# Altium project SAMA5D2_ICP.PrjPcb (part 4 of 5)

## Sheet 10 - CAN & WiFi BT.SchDoc
size B; CompanyName: Microchip Technology Inc.; Organization: Microchip Technology; Address1: 2355 West Chandler Blvd.; Address2: Chandler, AZ  85224; Address4: USA; DocumentNumber: 11; SheetNumber: 11; SheetTotal: 15; SheetTitle: CAN & WiFi/BT
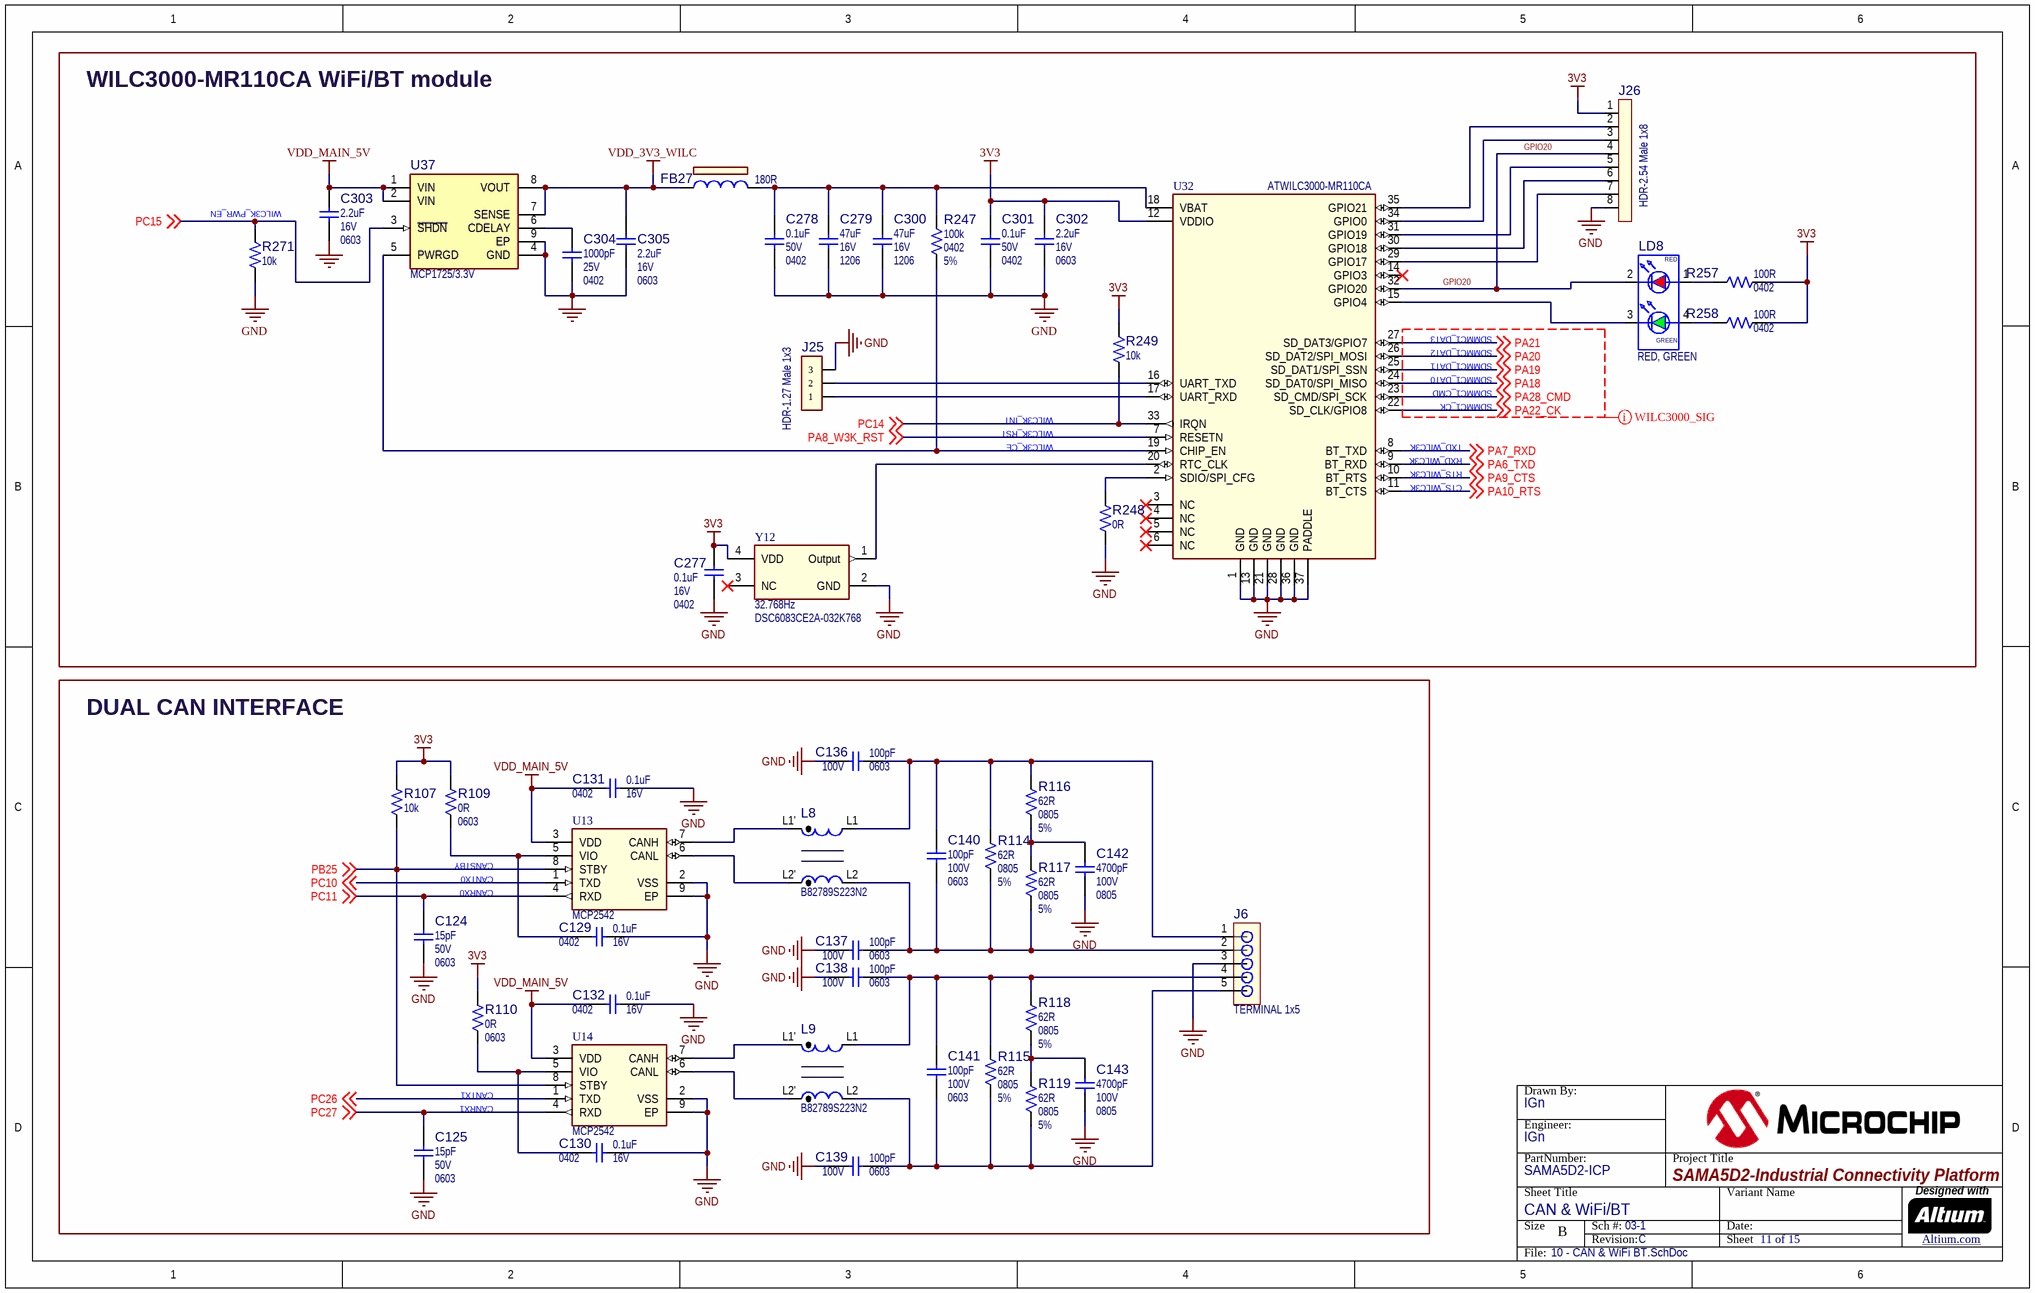
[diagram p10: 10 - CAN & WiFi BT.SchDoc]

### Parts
(Parts that share a designator on the sheet are numbered #1, #2 ... from top to bottom, then left to right.)
?#11  (no value)  (graphical)
C124  value 15pF  Voltage: 50V  Package: 0603  [CAP_C_0603]  (hidden comment: Capacitor NP)
C125  value 15pF  Voltage: 50V  Package: 0603  [CAP_C_0603]  (hidden comment: Capacitor NP)
C129  value 0.1uF  Voltage: 16V  Package: 0402  [CAP_C_0402]  (hidden comment: Capacitor NP)
C130  value 0.1uF  Voltage: 16V  Package: 0402  [CAP_C_0402]  (hidden comment: Capacitor NP)
C131  value 0.1uF  Voltage: 16V  Package: 0402  [CAP_C_0402]  (hidden comment: Capacitor NP)
C132  value 0.1uF  Voltage: 16V  Package: 0402  [CAP_C_0402]  (hidden comment: Capacitor NP)
C136  value 100pF  Voltage: 100V  Package: 0603  [CAP_C_0603]  (hidden comment: Capacitor NP)
C137  value 100pF  Voltage: 100V  Package: 0603  [CAP_C_0603]  (hidden comment: Capacitor NP)
C138  value 100pF  Voltage: 100V  Package: 0603  [CAP_C_0603]  (hidden comment: Capacitor NP)
C139  value 100pF  Voltage: 100V  Package: 0603  [CAP_C_0603]  (hidden comment: Capacitor NP)
C140  value 100pF  Voltage: 100V  Package: 0603  [CAP_C_0603]  (hidden comment: Capacitor NP)
C141  value 100pF  Voltage: 100V  Package: 0603  [CAP_C_0603]  (hidden comment: Capacitor NP)
C142  value 4700pF  Voltage: 100V  Package: 0805  [CAP_C_0805]  (hidden comment: Capacitor NP)
C143  value 4700pF  Voltage: 100V  Package: 0805  [CAP_C_0805]  (hidden comment: Capacitor NP)
C277  value 0.1uF  Voltage: 16V  Package: 0402  [CAP_C_0402]  (hidden comment: Capacitor NP)
C278  value 0.1uF  Voltage: 50V  Package: 0402  [CAP_C_0402]  (hidden comment: Capacitor NP)
C279  value 47uF  Voltage: 16V  Package: 1206  [CAP_C_1206]  (hidden comment: Capacitor NP)
C300  value 47uF  Voltage: 16V  Package: 1206  [CAP_C_1206]  (hidden comment: Capacitor NP)
C301  value 0.1uF  Voltage: 50V  Package: 0402  [CAP_C_0402]  (hidden comment: Capacitor NP)
C302  value 2.2uF  Voltage: 16V  Package: 0603  [CAP_C_0603]  (hidden comment: Capacitor NP)
C303  value 2.2uF  Voltage: 16V  Package: 0603  [CAP_C_0603]  (hidden comment: Capacitor NP)
C304  value 1000pF  Voltage: 25V  Package: 0402  [CAP_C_0402]  (hidden comment: Capacitor NP)
C305  value 2.2uF  Voltage: 16V  Package: 0603  [CAP_C_0603]  (hidden comment: Capacitor NP)
FB27  value 180R  [IND_C_0603]  (hidden comment: Ferrite Bead)
J6  value TERMINAL 1x5  [CON_TERMINAL_3.81_1x5_TH_RA_PHO_1727049]  (hidden comment: CON TERM BLK 1x5 TH Mount)
J25  value HDR-1.27 Male 1x3  [HDR_M_1.27_1x3]  (hidden comment: Header 1x3)
J26  value HDR-2.54 Male 1x8  [HDR_M_2.54_1x8]  (hidden comment: Header 1x8)
L8  value B82789S223N2  [IND_EP_SIMDAD_1812]  (hidden comment: Inductor Choke)
L9  value B82789S223N2  [IND_EP_SIMDAD_1812]  (hidden comment: Inductor Choke)
LD8  value RED, GREEN  [LED_DUAL_SMD_2x1.25mm]  (hidden comment: LED DUAL 4 pin)
R107  value 10k  [RES_C_0402]  (hidden comment: Resistor)
R109  value 0R  Package: 0603  [RES_C_0603]  (hidden comment: Resistor)
R110  value 0R  Package: 0603  [RES_C_0603]  (hidden comment: Resistor)
R114  value 62R  Package: 0805  Tolerance: 5%  [RES_C_0805]  (hidden comment: Resistor)
R115  value 62R  Package: 0805  Tolerance: 5%  [RES_C_0805]  (hidden comment: Resistor)
R116  value 62R  Package: 0805  Tolerance: 5%  [RES_C_0805]  (hidden comment: Resistor)
R117  value 62R  Package: 0805  Tolerance: 5%  [RES_C_0805]  (hidden comment: Resistor)
R118  value 62R  Package: 0805  Tolerance: 5%  [RES_C_0805]  (hidden comment: Resistor)
R119  value 62R  Package: 0805  Tolerance: 5%  [RES_C_0805]  (hidden comment: Resistor)
R247  value 100k  Package: 0402  Tolerance: 5%  [RES_C_0402]  (hidden comment: Resistor)
R248  value 0R  [RES_C_0603]  (hidden comment: Resistor)
R249  value 10k  [RES_C_0402]  (hidden comment: Resistor)
R257  value 100R  Package: 0402  [RES_C_0402]  (hidden comment: Resistor)
R258  value 100R  Package: 0402  [RES_C_0402]  (hidden comment: Resistor)
R271  value 10k  [RES_C_0402]  (hidden comment: Resistor)
U13  value MCP2542  [DFN-8_3x3_EP2.4X1.55]  (hidden comment: MCP2542 DFN-8)
U14  value MCP2542  [DFN-8_3x3_EP2.4X1.55]  (hidden comment: MCP2542 DFN-8)
U32  value ATWILC3000-MR110CA  [MODULE ATWILC3000-MR110CA]  (hidden comment: MODULE ATWILC3000-MR110CA)
U37  value MCP1725/3.3V  [DFN-8_2x3]  (hidden comment: MCP172X FIX DFN-8)
Y12  value 32.768Hz  Manufacturer Part Number 1: DSC6083CE2A-032K768  [OSCILLATOR_DSC1001_L3.2W2.5H0.85]  (hidden comment: OSC_DSC6083CE2A_3225)

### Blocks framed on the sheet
WILC3000-MR110CA WiFi/BT module: C277-C279 C300-C305 FB27 J25 J26 LD8 R247-R249 R257 R258 R271 U32 U37 Y12
DUAL CAN INTERFACE: C124 C125 C129-C132 C136-C143 J6 L8 L9 R107 R109 R110 R114-R119 U13 U14

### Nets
3V3: C277.2 C301.1 C302.2 J26.1 R107.2 R109.2 R110.2 R249.2 R257.2 R258.2 U32.12(VDDIO) Y12.4(VDD)
GND: C124.1 C125.1 C129.1 C130.1 C131.1 C132.1 C136.2 C137.2 C138.2 C139.2 C142.1 C143.1 C277.1 C278.2 C279.2 C300.2 C301.2 C302.1 C303.2 C304.1 C305.1 J6.3 J25.3 J26.8 R248.2 R271.1 U13.2(VSS) U13.9(EP) U14.2(VSS) U14.9(EP) U32.1(GND) U32.13(GND) U32.21(GND) U32.28(GND) U32.36(GND) U32.37(PADDLE) U37.4(GND) U37.9(EP) Y12.2(GND)
VDD_3V3_WILC: C305.2 FB27.1 U37.7(SENSE) U37.8(VOUT)
VDD_MAIN_5V: C131.2 C132.2 C303.1 U13.3(VDD) U14.3(VDD) U37.1(VIN) U37.2(VIN)
GPIO20: J26.4 LD8.2(K1) U32.32(GPIO20)
PA6_TXD: U32.9(BT_RXD) ; off-sheet PA6_TXD
PA7_RXD: U32.8(BT_TXD) ; off-sheet PA7_RXD
PA8_W3K_RST: U32.7(RESETN) ; off-sheet PA8_W3K_RST
PA9_CTS: U32.10(BT_RTS) ; off-sheet PA9_CTS
PA10_RTS: U32.11(BT_CTS) ; off-sheet PA10_RTS
PA18: U32.24(SD_DAT0/SPI_MISO) ; off-sheet PA18
PA19: U32.25(SD_DAT1/SPI_SSN) ; off-sheet PA19
PA20: U32.26(SD_DAT2/SPI_MOSI) ; off-sheet PA20
PA21: U32.27(SD_DAT3/GPIO7) ; off-sheet PA21
PA22_CK: U32.22(SD_CLK/GPIO8) ; off-sheet PA22_CK
PA28_CMD: U32.23(SD_CMD/SPI_SCK) ; off-sheet PA28_CMD
PB25: R107.1 U13.8(STBY) U14.8(STBY) ; off-sheet PB25
PC10: U13.1(TXD) ; off-sheet PC10
PC11: C124.2 U13.4(RXD) ; off-sheet PC11
PC14: R249.1 U32.33(IRQN) ; off-sheet PC14
PC15: R271.2 U37.3(~{SHDN}) ; off-sheet PC15
PC26: U14.1(TXD) ; off-sheet PC26
PC27: C125.2 U14.4(RXD) ; off-sheet PC27
NetC129_2: C129.2 R109.1 U13.5(VIO)
NetC130_2: C130.2 R110.1 U14.5(VIO)
NetC136_1: C136.1 C140.2 J6.1 L8.L1 R114.2 R116.2
NetC137_1: C137.1 C140.1 J6.2 L8.L2 R114.1 R117.1
NetC138_1: C138.1 C141.2 J6.4 L9.L1 R115.2 R118.2
NetC139_1: C139.1 C141.1 J6.5 L9.L2 R115.1 R119.1
NetC142_2: C142.2 R116.1 R117.2
NetC143_2: C143.2 R118.1 R119.2
NetC278_1: C278.1 C279.1 C300.1 FB27.2 R247.2 U32.18(VBAT)
NetC304_2: C304.2 U37.6(CDELAY)
NetJ25_1: J25.1 U32.17(UART_RXD)
NetJ25_2: J25.2 U32.16(UART_TXD)
NetJ26_2: J26.2 U32.35(GPIO21)
NetJ26_3: J26.3 U32.34(GPIO0)
NetJ26_5: J26.5 U32.31(GPIO19)
NetJ26_6: J26.6 U32.30(GPIO18)
NetJ26_7: J26.7 U32.29(GPIO17)
NetL8_L1': L8.L1' U13.7(CANH)
NetL8_L2': L8.L2' U13.6(CANL)
NetL9_L1': L9.L1' U14.7(CANH)
NetL9_L2': L9.L2' U14.6(CANL)
NetLD8_1: LD8.1(A1) R257.1
NetLD8_3: LD8.3(K2) U32.15(GPIO4)
NetLD8_4: LD8.4(A2) R258.1
NetR247_1: R247.1 U32.19(CHIP_EN) U37.5(PWRGD)
NetR248_1: R248.1 U32.2(SDIO/SPI_CFG)
NetU32_20: U32.20(RTC_CLK) Y12.1(Output)

Not connected (* = marked no-connect by the designer): U32 3(NC)* 4(NC)* 5(NC)* 6(NC)* 14(GPIO3)*; Y12 3(NC)*

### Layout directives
net class WILC300_SIG: PA18, PA19, PA20, PA21, PA22_CK, PA28_CMD

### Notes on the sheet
- (near R271) WILC3K_PWR_EN
- SDMMC1_DAT3
- SDMMC1_DAT2
- SDMMC1_DAT1
- SDMMC1_DAT0
- WILC3K_INT
- WILC3K_RST
- WILC3K_CE
- (near U32) TXD_WILC3K
- SDMMC1_CMD
- SDMMC1_CK
- (near U32) RXD_WILC3K
- (near U32) RTS_WILC3K
- (near U32) CTS_WILC3K
- CANRX0
- CANTX0
- CANSTBY
- CANRX1
- CANTX1

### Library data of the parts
?#11 = Title Block B
C124 C125 = CAP0121: Capacitor; Manufacturer 1: TDK; Manufacturer Part Number 1: C1608C0G1H150J; Description_: CAP CER 15pF 50V 5% NP0 SMD 0603; Dev Tools Status: Production; Tolerance: 5%; Temperature Coeffcient: NP0; Type: Ceramic; Populated: Yes
C129-C132 C277 = CAP1033: Capacitor; Manufacturer 1: Murata; Manufacturer Part Number 1: GRM155R71C104KA88D; Description_: CAP CER 0.1uF 16V 10% X7R SMD 0402; Dev Tools Status: Production; Tolerance: 10%; Temperature Coeffcient: X7R; Type: Ceramic; Owner: Sompoch Loboonlert; Populated: Yes
C136-C139 = CAP1112: Capacitor; Manufacturer 1: KEMET; Manufacturer Part Number 1: C0603C101J1GACTU; Description_: CAP CER 100pF 100V 5% C0G SMD 0603; Dev Tools Status: Production; Tolerance: 5%; Temperature Coeffcient: C0G, NP0; Type: Ceramic; Populated: YES; Owner: Mihai T(M91442)
C140 C141 = CAP1112: Capacitor; Manufacturer 1: KEMET; Manufacturer Part Number 1: C0603C101J1GACTU; Description_: CAP CER 100pF 100V 5% C0G SMD 0603; Dev Tools Status: Production; Tolerance: 5%; Temperature Coeffcient: C0G, NP0; Type: Ceramic; Populated: DNP; Owner: Mihai T(M91442)
C142 C143 = CAP1272: Capacitor; Manufacturer 1: TDK Corporation; Manufacturer Part Number 1: C2012X7R2A472K085AE; Description_: CAP CER 4700pF 100V 10% X7R SMD 0805; Dev Tools Status: Production; Tolerance: 10%; Temperature Coeffcient: X7R; Type: Ceramic; Populated: YES; Owner: Jairuz Agang-ang
C278 C301 = CAP1463: Capacitor; Manufacturer 1: TDK Corporation; Manufacturer Part Number 1: C1005X7R1H104K050BB; Description_: CAP CER 0.1uF 50V 10% X7R SMD 0402; Dev Tools Status: Production; Tolerance: 10%; Temperature Coeffcient: X7R; Type: Ceramic; Owner: Jamus Griego; Populated: YES
C279 = CAP1331: Capacitor; Manufacturer 1: TDK Corporation; Manufacturer Part Number 1: C3216X5R1C476M160AB; Description_: CAP CER 47uF 16V 20% X5R SMD 1206; Dev Tools Status: Production; Tolerance: 20%; Temperature Coeffcient: X5R; Type: Ceramic; Owner: Bogdan Popescu; Populated: YES
C300 = CAP1331: Capacitor; Manufacturer 1: TDK Corporation; Manufacturer Part Number 1: C3216X5R1C476M160AB; Description_: CAP CER 47uF 16V 20% X5R SMD 1206; Dev Tools Status: Production; Tolerance: 20%; Temperature Coeffcient: X5R; Type: Ceramic; Owner: Bogdan Popescu; Populated: DNP
C302 C303 C305 = CAP0597: Capacitor; Manufacturer 1: TDK; Manufacturer Part Number 1: C1608X5R1C225K; Description_: CAP CER 2.2uF 16V 10% X5R SMD 0603; Dev Tools Status: Production; Tolerance: 10%; Temperature Coeffcient: X5R; Type: Ceramic; Populated: Yes
C304 = CAP0566: Capacitor; Manufacturer 1: TDK; Manufacturer Part Number 1: C1005C0G1E102J; Description_: CAP CER 1000pF 25V 5% C0G SMD 0402; Dev Tools Status: Production; Tolerance: 5%; Temperature Coeffcient: C0G; Type: Ceramic; Populated: Yes
FB27 = IND1453: FERRITE 180R 1.5A SMD 0603; Manufacturer 1: Murata Electronics North America; Manufacturer Part Number 1: BLM18PG181SN1D; Dev Tools Status: Production; Owner: Dragos Danaila; DCR: 0.09R; Test Frequency: 100MHz; Populated: YES
J6 = CON1693: Manufacturer 1: Phoenix Contact; Manufacturer Part Number 1: 1727049; Description_: CON TERMINAL 3.81mm 1x5 Female 16-30AWG 13.5A TH R/A; Dev Tools Status: Design; Owner: Ciprian Abramov; Voltage: 300; Current: 13.5A; Populated: YES
J25 = CON1345: Manufacturer 1: Samtec; Manufacturer Part Number 1: TMS-103-01-G-S; Description_: CON HDR-1.27 Male 1x3 Gold TH; Dev Tools Status: Production; Owner: Jamus Griego; Populated: DNP
J26 = CON1302: CON HDR-2.54 Female 1x8 Gold TH; Manufacturer 1: FCI; Manufacturer Part Number 1: 68001-108HLF; Description_: CON HDR-2.54 Male 1x8 Gold 5.84MH TH; Dev Tools Status: Production; Owner: Bogdan Popescu; Populated: DNP
L8 L9 = IND1156: Inductor; Manufacturer 1: EPCOS Inc; Description_: CHOKE DBL 22UH 250MA TIN SMD; Dev Tools Status: Design; Owner: Stephen Humberd; RMS Current: 250mA; Populated: YES
LD8 = DIODE1110: LED; Manufacturer 1: Kingbright Corp; Manufacturer Part Number 1: APHBM2012SURKCGKC; Description_: DIO LED BI RED, GREEN 1.95V, 2.1V 30mA 0805; Dev Tools Status: Production; Type: LED Bicolor; Forward Current: 30mA; Power: 75mW; Reverse Current: 10uA; Owner: Bogdan P (M91398); Populated: Yes
R107 R249 = RSMT1019: Manufacturer 1: Panasonic; Manufacturer Part Number 1: ERJ-2RKF1002X; Tolerance: 1%; Description_: RES TKF 10k 1% 1/10W SMD 0402; Dev Tools Status: Production; Voltage: 50V; Temperature Coeffcient: 100ppm/C; Power: 1/10W; Owner: Brent Lanphear; Populated: Yes
R109 R110 R248 = RSMT0001: Manufacturer 1: Panasonic; Manufacturer Part Number 1: ERJ-3GSY0R00V; Description_: RES TKF 0R 1/10W SMD 0603; Dev Tools Status: Production; Power: 1/10W; Populated: Yes
R114 R115 = RSMT1232: Manufacturer 1: Panasonic Electronic Components; Manufacturer Part Number 1: ERJ-P06J620V; Description_: RES TKF 62R 5% 1/2W SMD 0805; Dev Tools Status: Design; Voltage: 600V; Temperature Coeffcient: 200ppm; Current: 90mA; Power: 1/2W; Owner: Dragos Danaila; Populated: DNP
R116-R119 = RSMT1232: Manufacturer 1: Panasonic Electronic Components; Manufacturer Part Number 1: ERJ-P06J620V; Description_: RES TKF 62R 5% 1/2W SMD 0805; Dev Tools Status: Design; Voltage: 600V; Temperature Coeffcient: 200ppm; Current: 90mA; Power: 1/2W; Owner: Dragos Danaila; Populated: YES
R247 = RES2196: Manufacturer 1: Yageo; Manufacturer Part Number 1: RC0402JR-07100KL; Description_: RES TKF 100k 5% 1/16W SMD 0402; Dev Tools Status: Design; Temperature Coeffcient: 100ppm/C; Power: 1/16W; Owner: Ilie Galan; Populated: YES
R257 R258 = RES1436: Manufacturer 1: Panasonic Electronic Components; Manufacturer Part Number 1: ERJ-2RKF1000X; Tolerance: 1%; Description_: RES TKF 100R 1% 1/10W SMD 0402; Dev Tools Status: Production; Temperature Coeffcient: ±100ppm/°C; Power: 1/10W; Populated: YES
R271 = RSMT1019: Manufacturer 1: Panasonic; Manufacturer Part Number 1: ERJ-2RKF1002X; Tolerance: 1%; Description_: RES TKF 10k 1% 1/10W SMD 0402; Dev Tools Status: Production; Voltage: 50V; Temperature Coeffcient: 100ppm/C; Power: 1/10W; Owner: Brent Lanphear; Populated: DNP
U13 U14 = MIC7856: Manufacturer 1: Microchip Technology; Manufacturer Part Number 1: MCP2542FDT-E/MF; Description_: MCHP INTERFACE CAN MCP2542FDT-E/MF DFN-8; MAPS Description: CAN Transceiver; Dev Tools Status: Design; Owner: Ilie Galan; MPC: V7BC6YA7XA00; LeadContent: Pb-FREE; PackingMedia: T/R; Stage: REL; LeadCount: 8; PackageWidth: 3x3x0.9mm; ForceMinOrderQtyMult: True; MinOrderQty: 1; TempRange: -40C to +125C; tblDeviceFamilyID: 5993; DeviceType: Transceiver; OperatingVoltageMin: 4.5; OperatingVoltageMax: 5.5; StandbyCurrentMax: 15; OperatingCurrentMax: 10; PropDelayMax: 120; ShortCircuit: -58 to +58; TransientVoltage: -150 to +100; ESD: 13; ThermalShutdown: Yes; Masks: 0; CMR: +/-12; Comments: Flexible Data Rate Capable
U32 = MIC7405: Manufacturer 1: Microchip Technology; Description_: MCHP RF WI-FI 802.11b/g/n ATWILC3000-MR110CA; MAPS Description: SmartConnect WILC3000-MR110CA Module; Dev Tools Status: Design; Owner: Ilie Galan; tblDeviceFamilyID: 11256; FrequencyRange: 2.412-2.472 MHz; MaxSpeedMHz: 0; Populated: DNP
U37 = MIC2599: LDO; Manufacturer 1: Microchip; Manufacturer Part Number 1: MCP1725T-3302E/MC; Description_: MCHP ANALOG LDO 3.3V MCP1725T-3302E/MC DFN-8; MAPS Description: 500MA, LOW VOLTAGE LDO; Dev Tools Status: Production; MPC: GEAH1YB3XA33; LeadContent: Pb-FREE; PackingMedia: T/R; Stage: REL; LeadCount: 8; PackageWidth: 2x3x0.9mm; ForceMinOrderQtyMult: True; MinOrderQty: 1; TempRange: -40C to +125C; tblDeviceFamilyID: 1781; Populated: Yes
Y12 = MIC7476: Manufacturer 1: Microchip Technology; Description_: MCHP CLOCK OSCILLATOR SINGLE 32.768Hz DSC6083CE2A-032K768 SMD DFN-4; Dev Tools Status: Design; Owner: Dragos Danaila; Populated: YES

## Sheet 11 - On Board Memories.SchDoc
size B; CompanyName: Microchip Technology Inc.; Organization: Microchip Technology; Address1: 2355 West Chandler Blvd.; Address2: Chandler, AZ  85224; Address4: USA; DocumentNumber: 12; SheetNumber: 12; SheetTotal: 15; SheetTitle: On Board Memories
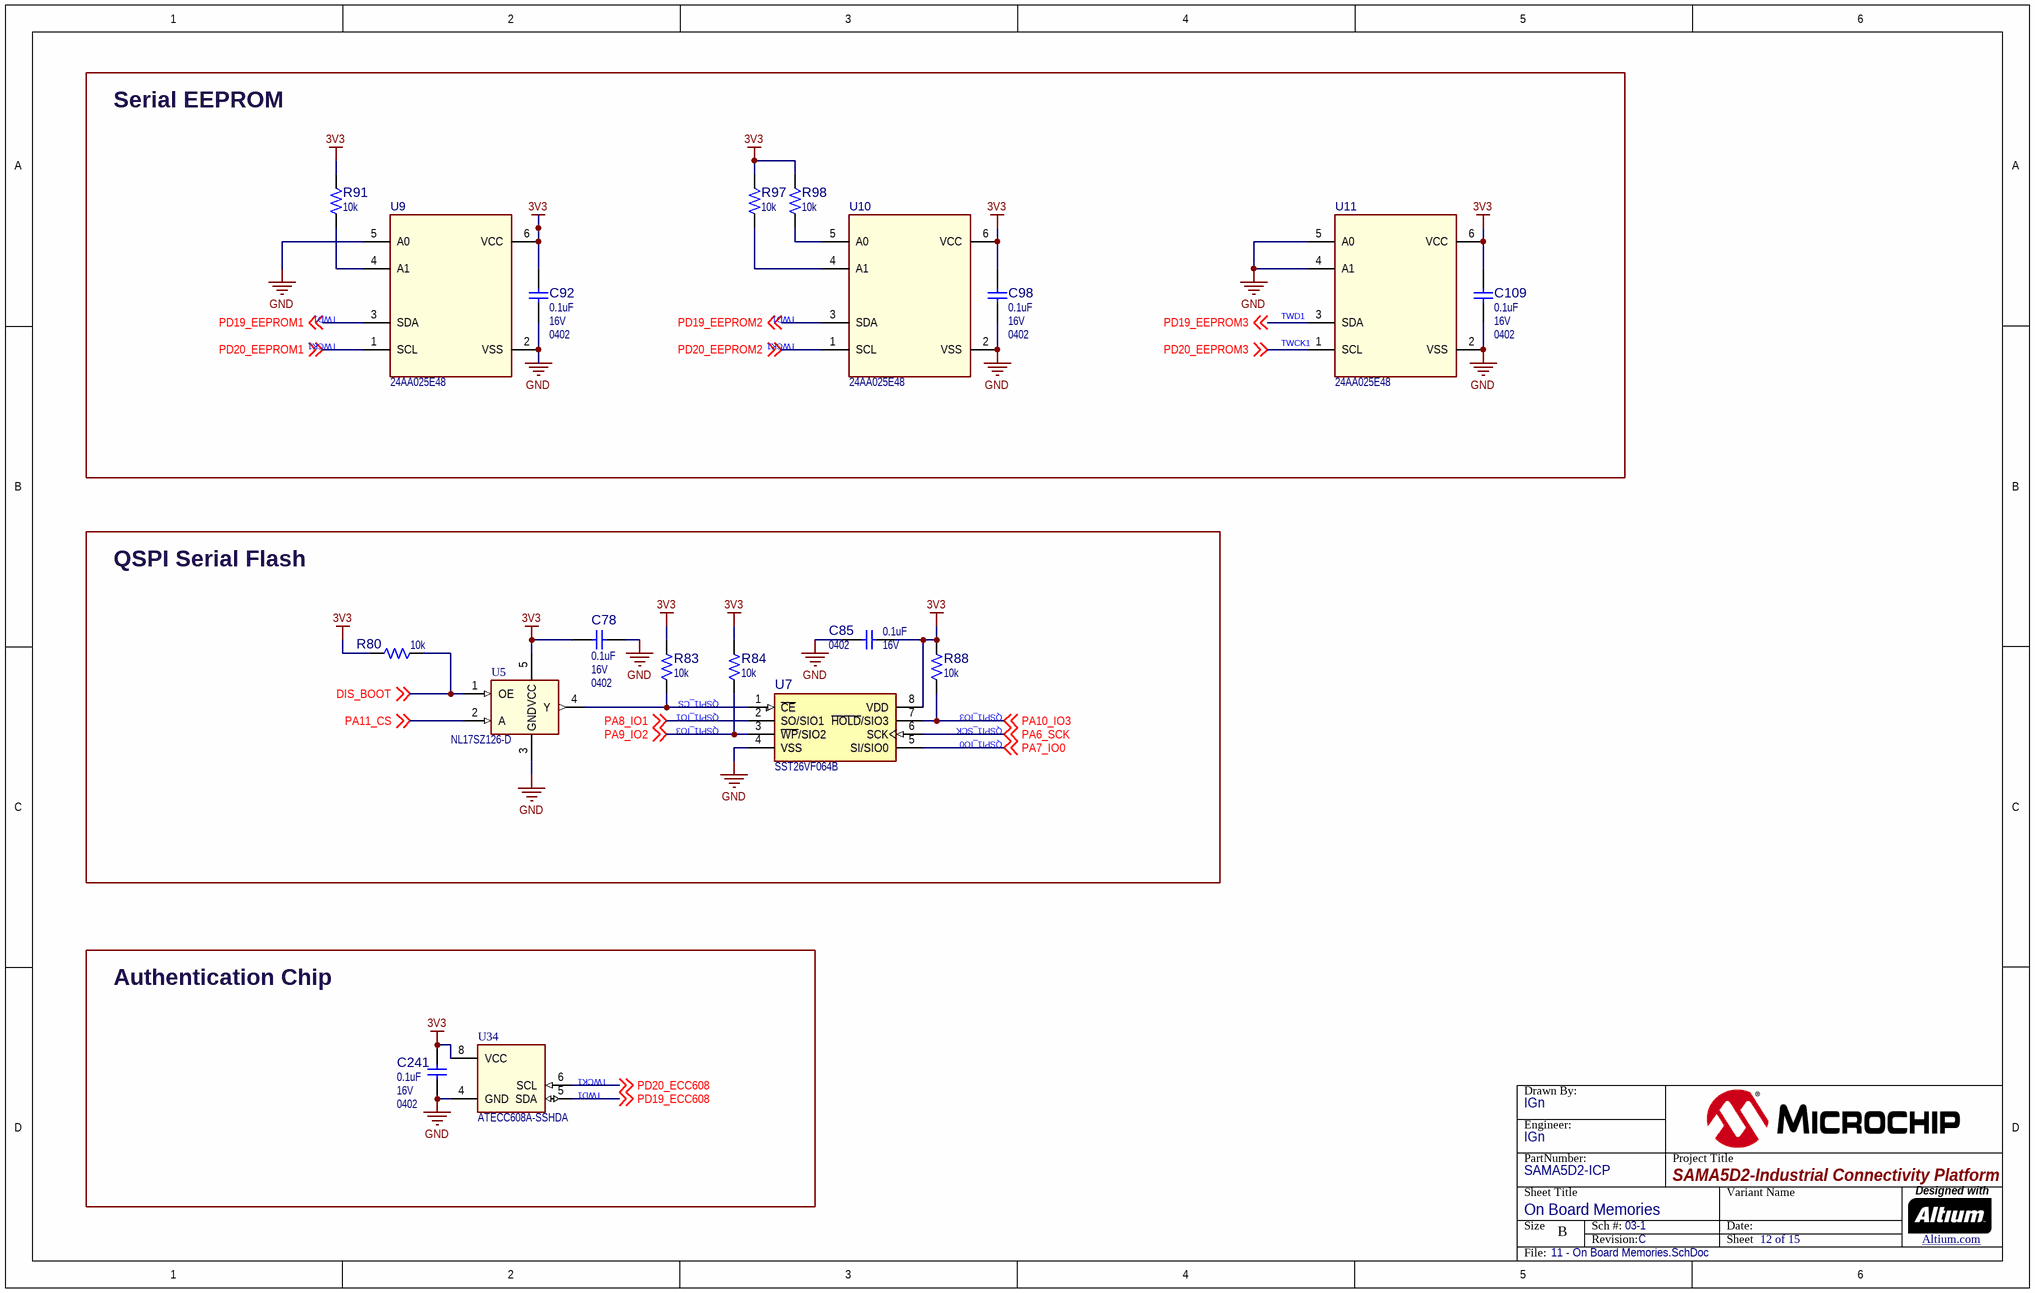
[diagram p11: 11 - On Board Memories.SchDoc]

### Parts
(Parts that share a designator on the sheet are numbered #1, #2 ... from top to bottom, then left to right.)
?#12  (no value)  (graphical)
C78  value 0.1uF  Voltage: 16V  Package: 0402  [CAP_C_0402]  (hidden comment: Capacitor NP)
C85  value 0.1uF  Voltage: 16V  Package: 0402  [CAP_C_0402]  (hidden comment: Capacitor NP)
C92  value 0.1uF  Voltage: 16V  Package: 0402  [CAP_C_0402]  (hidden comment: Capacitor NP)
C98  value 0.1uF  Voltage: 16V  Package: 0402  [CAP_C_0402]  (hidden comment: Capacitor NP)
C109  value 0.1uF  Voltage: 16V  Package: 0402  [CAP_C_0402]  (hidden comment: Capacitor NP)
C241  value 0.1uF  Voltage: 16V  Package: 0402  [CAP_C_0402]  (hidden comment: Capacitor NP)
R80  value 10k  [RES_C_0402]  (hidden comment: Resistor)
R83  value 10k  [RES_C_0402]  (hidden comment: Resistor)
R84  value 10k  [RES_C_0402]  (hidden comment: Resistor)
R88  value 10k  [RES_C_0402]  (hidden comment: Resistor)
R91  value 10k  [RES_C_0402]  (hidden comment: Resistor)
R97  value 10k  [RES_C_0402]  (hidden comment: Resistor)
R98  value 10k  [RES_C_0402]  (hidden comment: Resistor)
U5  value NL17SZ126-D  [SOT-353]  (hidden comment: NL17SZ126-D SOT-353)
U7  value SST26VF064B  [SOIJ-8]  (hidden comment: SST26VFXXX SOIC-8_WSON-8_SOIJ-8)
U9  value 24AA025E48  [SOT-23-6]  (hidden comment: 24XXXX SOT-23-6)
U10  value 24AA025E48  [SOT-23-6]  (hidden comment: 24XXXX SOT-23-6)
U11  value 24AA025E48  [SOT-23-6]  (hidden comment: 24XXXX SOT-23-6)
U34  value ATECC608A-SSHDA  [SOIC-8]  (hidden comment: ATECC608A-SSHDA-B SOIC-8)

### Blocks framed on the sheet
Serial EEPROM: C92 C98 C109 R91 R97 R98 U9-U11
QSPI Serial Flash: C78 C85 R80 R83 R84 R88 U5 U7
Authentication Chip: C241 U34

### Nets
3V3: C78.2 C85.2 C92.2 C98.2 C109.2 C241.2 R80.2 R83.2 R84.2 R88.2 R91.1 R97.2 R98.2 U5.5(VCC) U7.8(VDD) U9.6(VCC) U10.6(VCC) U11.6(VCC) U34.8(VCC)
GND: C78.1 C85.1 C92.1 C98.1 C109.1 C241.1 U5.3(GND) U7.4(VSS) U9.2(VSS) U9.5(A0) U10.2(VSS) U11.2(VSS) U11.4(A1) U11.5(A0) U34.4(GND)
DIS_BOOT: R80.1 U5.1(OE) ; off-sheet DIS_BOOT
PA6_SCK: U7.6(SCK) ; off-sheet PA6_SCK
PA7_IO0: U7.5(SI/SIO0) ; off-sheet PA7_IO0
PA8_IO1: U7.2(SO/SIO1) ; off-sheet PA8_IO1
PA9_IO2: R84.1 U7.3(~{WP}/SIO2) ; off-sheet PA9_IO2
PA10_IO3: R88.1 U7.7(~{HOLD}/SIO3) ; off-sheet PA10_IO3
PA11_CS: U5.2(A) ; off-sheet PA11_CS
PD19_ECC608: U34.5(SDA) ; off-sheet PD19_ECC608
PD19_EEPROM1: U9.3(SDA) ; off-sheet PD19_EEPROM1
PD19_EEPROM2: U10.3(SDA) ; off-sheet PD19_EEPROM2
PD19_EEPROM3: U11.3(SDA) ; off-sheet PD19_EEPROM3
PD20_ECC608: U34.6(SCL) ; off-sheet PD20_ECC608
PD20_EEPROM1: U9.1(SCL) ; off-sheet PD20_EEPROM1
PD20_EEPROM2: U10.1(SCL) ; off-sheet PD20_EEPROM2
PD20_EEPROM3: U11.1(SCL) ; off-sheet PD20_EEPROM3
NetR83_1: R83.1 U5.4(Y) U7.1(~{CE})
NetR91_2: R91.2 U9.4(A1)
NetR97_1: R97.1 U10.4(A1)
NetR98_1: R98.1 U10.5(A0)

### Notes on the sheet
- (near U9) TWD1
- (near U9) TWCK1
- (near U10) TWD1
- (near U10) TWCK1
- (near U11) TWD1
- (near U11) TWCK1
- QSPI1_IO1
- QSPI1_CS
- (near R88) QSPI1_IO3
- QSPI1_IO3
- QSPI1_IO0
- QSPI1_SCK
- (near U34) TWD1
- (near U34) TWCK1

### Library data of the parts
?#12 = Title Block B
C78 C85 C92 C98 C109 C241 = CAP1033: as C129-C132 on sheet 10 - CAN & WiFi BT
R80 R83 R84 R88 R91 R97 R98 = RSMT1019: as R107 on sheet 10 - CAN & WiFi BT
U5 = IC1434: Manufacturer 1: ON Semiconductor; Manufacturer Part Number 1: NL17SZ126DFT2G; MCHP-ID: IC1434; Description_: IC BUFFER NL17SZ126DFT2G TRI-ST NON-INV SOT-353; Dev Tools Status: Production; Vin: -0.5V to +7.0V; Owner: Alexandru Chiser - M19201; Populated: YES
U7 = MIC6216: SQI Serial Flash; Manufacturer 1: Microchip Technology; Manufacturer Part Number 1: SST26VF064B-104I/SM; Description_: MCHP SERIAL FLASH SST26VF064B-104I/SM SOIJ-8; MAPS Description: 64Mb 2.3V TO 3.6V SQI Flash Memory; Dev Tools Status: Production; Owner: Sompoch Loboonlert; MPC: S01027C3XA23; PackingMedia: TUBE; TempRange: -40C to +85C; Stage: REL; LeadCount: 8; PackageWidth: .208in; ForceMinOrderQtyMult: False; MinOrderQty: 0; LeadContent: Pb-FREE; Busmodes: SPI,SDI,SQI; MemorySize: 64Mb; OpVoltMin: 2,3; OpVoltMax: 3,6; MaxClockFreq: 104 MHz; PageSize_B: 256; WPScheme: Full Array; Endurance: 100,000; Populated: YES
U9-U11 = MIC7407: Manufacturer 1: Microchip Technology; Manufacturer Part Number 1: 24AA025E48T-I/OT; Description_: MCHP MEMORY SERIAL EEPROM 2Kb I2C 24AA025E48T-I/OT SOT-23-6; MAPS Description: 24AA025E48 device, which will be a pre-prog. version of the 24AA024H (DFAX7).; Dev Tools Status: Design; Owner: Ciprian Abramov; MPC: DFAX7TC8XD00; PackingMedia: T/R; TempRange: -40C to +85C; Stage: REL; LeadCount: 6; ForceMinOrderQtyMult: True; MinOrderQty: 50; LeadContent: Pb-FREE; MemorySize: 2K; OpVoltMin: 1.7; OpVoltMax: 5.5; MaxClockFreq: 400 kHz; AddressPins: 3; PageSize_B: 16; WPScheme: Half Array; MemoryOrg: x8; Endurance: 1,000,000; Comments: memory size changed from 2KBits to 2K; Populated: YES
U34 = MIC7054: Manufacturer 1: Microchip Technology; Description_: MCHP MEMORY SERIAL EEPROM CRYPTO I2C ATECC608A-SSHDA-B SOIC-8; Dev Tools Status: Production; Owner: Mark Loper; Populated: YES

## Sheet 12 - Expansion connectors.SchDoc
size B; CompanyName: Microchip Technology Inc.; Organization: Microchip Technology; Address1: 2355 West Chandler Blvd.; Address2: Chandler, AZ  85224; Address4: USA; DocumentNumber: 13; SheetNumber: 13; SheetTotal: 15; SheetTitle: Expansion connectors
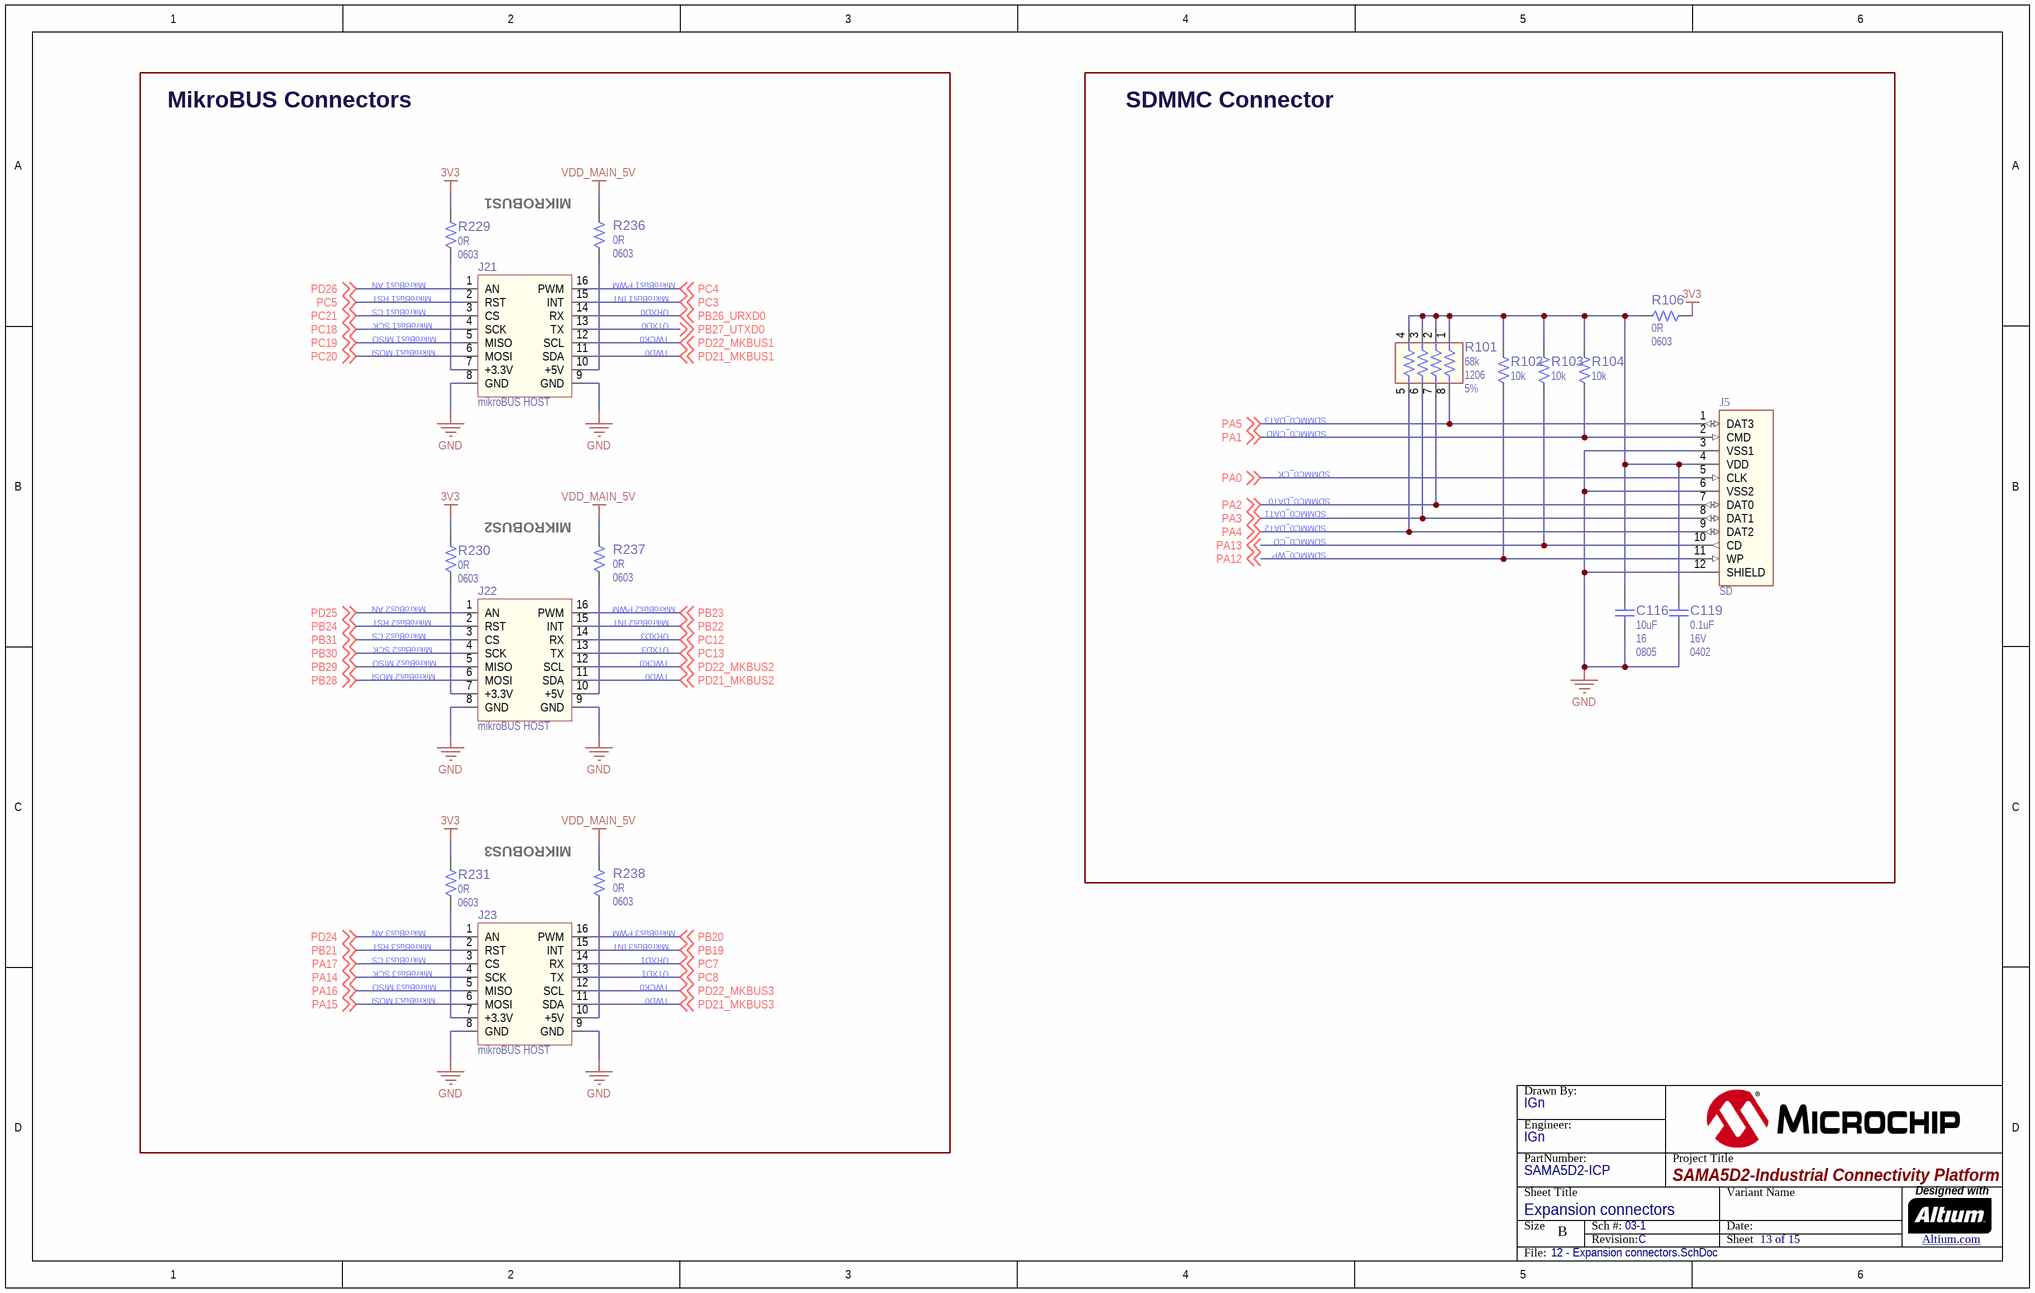
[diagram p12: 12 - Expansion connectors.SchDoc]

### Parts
(Parts that share a designator on the sheet are numbered #1, #2 ... from top to bottom, then left to right.)
?#13  (no value)  (graphical)
C116  value 10uF  Voltage: 16  Package: 0805  [CAP_C_0805]  (hidden comment: Capacitor NP)
C119  value 0.1uF  Voltage: 16V  Package: 0402  [CAP_C_0402]  (hidden comment: Capacitor NP)
J5  value SD  [10067847-001RLF]  (hidden comment: CON SD CARD 11P_amphenol)
J21  value mikroBUS HOST  [SOCKET_mikroBUS_F_2.54_2x8_V_25.4x21]  (hidden comment: SOCKET mikroBUS HOST)
J22  value mikroBUS HOST  [SOCKET_mikroBUS_F_2.54_2x8_V_25.4x21]  (hidden comment: SOCKET mikroBUS HOST)
J23  value mikroBUS HOST  [SOCKET_mikroBUS_F_2.54_2x8_V_25.4x21]  (hidden comment: SOCKET mikroBUS HOST)
R101  value 68k  Package: 1206  Tolerance: 5%  [RES_C_CAV_0603x4]  (hidden comment: Resistor Network 4-Ch)
R102  value 10k  [RES_C_0402]  (hidden comment: Resistor)
R103  value 10k  [RES_C_0402]  (hidden comment: Resistor)
R104  value 10k  [RES_C_0402]  (hidden comment: Resistor)
R106  value 0R  Package: 0603  [RES_C_0603]  (hidden comment: Resistor)
R229  value 0R  Package: 0603  [RES_C_0603]  (hidden comment: Resistor)
R230  value 0R  Package: 0603  [RES_C_0603]  (hidden comment: Resistor)
R231  value 0R  Package: 0603  [RES_C_0603]  (hidden comment: Resistor)
R236  value 0R  Package: 0603  [RES_C_0603]  (hidden comment: Resistor)
R237  value 0R  Package: 0603  [RES_C_0603]  (hidden comment: Resistor)
R238  value 0R  Package: 0603  [RES_C_0603]  (hidden comment: Resistor)

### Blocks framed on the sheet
MikroBUS Connectors: J21-J23 R229-R231 R236-R238
SDMMC Connector: C116 C119 J5 R101-R104 R106

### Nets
3V3: R106.1 R229.1 R230.1 R231.1
GND: C116.1 C119.1 J5.3(VSS1) J5.6(VSS2) J5.12(SHIELD) J21.8(GND) J21.9(GND) J22.8(GND) J22.9(GND) J23.8(GND) J23.9(GND)
VDD_MAIN_5V: R236.1 R237.1 R238.1
PA0: J5.5(CLK) ; off-sheet PA0
PA1: J5.2(CMD) R104.1 ; off-sheet PA1
PA2: J5.7(DAT0) R101.7 ; off-sheet PA2
PA3: J5.8(DAT1) R101.6 ; off-sheet PA3
PA4: J5.9(DAT2) R101.5 ; off-sheet PA4
PA5: J5.1(DAT3) R101.8 ; off-sheet PA5
PA12: J5.11(WP) R102.1 ; off-sheet PA12
PA13: J5.10(CD) R103.1 ; off-sheet PA13
PA14: J23.4(SCK) ; off-sheet PA14
PA15: J23.6(MOSI) ; off-sheet PA15
PA16: J23.5(MISO) ; off-sheet PA16
PA17: J23.3(CS) ; off-sheet PA17
PB19: J23.15(INT) ; off-sheet PB19
PB20: J23.16(PWM) ; off-sheet PB20
PB21: J23.2(RST) ; off-sheet PB21
PB22: J22.15(INT) ; off-sheet PB22
PB23: J22.16(PWM) ; off-sheet PB23
PB24: J22.2(RST) ; off-sheet PB24
PB26_URXD0: J21.14(RX) ; off-sheet PB26_URXD0
PB27_UTXD0: J21.13(TX) ; off-sheet PB27_UTXD0
PB28: J22.6(MOSI) ; off-sheet PB28
PB29: J22.5(MISO) ; off-sheet PB29
PB30: J22.4(SCK) ; off-sheet PB30
PB31: J22.3(CS) ; off-sheet PB31
PC3: J21.15(INT) ; off-sheet PC3
PC4: J21.16(PWM) ; off-sheet PC4
PC5: J21.2(RST) ; off-sheet PC5
PC7: J23.14(RX) ; off-sheet PC7
PC8: J23.13(TX) ; off-sheet PC8
PC12: J22.14(RX) ; off-sheet PC12
PC13: J22.13(TX) ; off-sheet PC13
PC18: J21.4(SCK) ; off-sheet PC18
PC19: J21.5(MISO) ; off-sheet PC19
PC20: J21.6(MOSI) ; off-sheet PC20
PC21: J21.3(CS) ; off-sheet PC21
PD21_MKBUS1: J21.11(SDA) ; off-sheet PD21_MKBUS1
PD21_MKBUS2: J22.11(SDA) ; off-sheet PD21_MKBUS2
PD21_MKBUS3: J23.11(SDA) ; off-sheet PD21_MKBUS3
PD22_MKBUS1: J21.12(SCL) ; off-sheet PD22_MKBUS1
PD22_MKBUS2: J22.12(SCL) ; off-sheet PD22_MKBUS2
PD22_MKBUS3: J23.12(SCL) ; off-sheet PD22_MKBUS3
PD24: J23.1(AN) ; off-sheet PD24
PD25: J22.1(AN) ; off-sheet PD25
PD26: J21.1(AN) ; off-sheet PD26
NetC116_2: C116.2 C119.2 J5.4(VDD) R101.1 R101.2 R101.3 R101.4 R102.2 R103.2 R104.2 R106.2
NetJ21_7: J21.7(+3.3V) R229.2
NetJ21_10: J21.10(+5V) R236.2
NetJ22_7: J22.7(+3.3V) R230.2
NetJ22_10: J22.10(+5V) R237.2
NetJ23_7: J23.7(+3.3V) R231.2
NetJ23_10: J23.10(+5V) R238.2

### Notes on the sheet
- (near R236) MIKROBUS1
- MikroBus1 AN
- MikroBus1 CS
- MikroBus1 RST
- URXD0
- MikroBus1 INT
- MikroBus1 PWM
- (near J21) MikroBus1 SCK
- (near J21) MikroBus1 MOSI
- (near J21) MikroBus1 MISO
- TWCK0
- TWD0
- UTXD0
- SDMMC0_CMD
- SDMMC0_DAT3
- SDMMC0_DAT1
- SDMMC0_DAT0
- SDMMC0_CK
- (near R237) MIKROBUS2
- SDMMC0_WP
- SDMMC0_CD
- SDMMC0_DAT2
- MikroBus2 AN
- MikroBus2 CS
- MikroBus2 RST
- (near J22) MikroBus2 SCK
- URXD3
- UTXD3
- MikroBus2 INT
- MikroBus2 PWM
- (near J22) MikroBus2 MOSI
- (near J22) MikroBus2 MISO
- (near R238) MIKROBUS3
- MikroBus3 AN
- MikroBus3 CS
- MikroBus3 RST
- (near J23) MikroBus3 SCK
- (near J23) MikroBus3 MISO
- URXD1
- UTXD1
- MikroBus3 INT
- MikroBus3 PWM
- (near J23) MikroBus3 MOSI

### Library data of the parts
?#13 = Title Block B
C116 = CAP1323: Capacitor; Manufacturer 1: Taiyo Yuden; Manufacturer Part Number 1: EMK212BB7106MG-T; Description_: CAP CER 10uF 16V 20% X7R SMD 0805; Dev Tools Status: Production; Tolerance: 20%; Temperature Coeffcient: X7R; Type: Ceramic; Owner: Rodger Griffith; Populated: YES
C119 = CAP1033: as C129-C132 on sheet 10 - CAN & WiFi BT
J5 = CON1752: Manufacturer 1: Amphenol FCI; Description_: 12 (9 + 3) Position Card Connector SD Surface Mount, Right Angle Gold; Dev Tools Status: Design; Owner: Dragos Danaila; Voltage: 17V; Current: 500mA; Populated: YES
J21-J23 = SKT1042: Manufacturer 1: Sullins Connector Solutions; Manufacturer Part Number 1: PPTC081LFBN-RC; Description_: SOCKET mikroBUS HOST DIP 16 TH; Dev Tools Status: Production; Owner: Stephen Humberd; Populated: YES
R101 = RNET1004: Resistor; Manufacturer 1: Yageo; Manufacturer Part Number 1: YC164-JR-0768KL; Description_: RES NET 68k 5% 62.5mW SMD 0603x4; Dev Tools Status: Production; Voltage: 50V; Temperature Coeffcient: 200ppm/C; Current: 1A; Power: 62.5mW; Owner: Alexandru Chiser - M19201; Populated: YES
R102-R104 = RSMT1019: as R107 on sheet 10 - CAN & WiFi BT
R106 R229-R231 = RSMT0001: as R109 on sheet 10 - CAN & WiFi BT
R236-R238 = RSMT0001: Manufacturer 1: Panasonic; Manufacturer Part Number 1: ERJ-3GSY0R00V; Description_: RES TKF 0R 1/10W SMD 0603; Dev Tools Status: Production; Power: 1/10W; Populated: YES

## Sheet 13 - User Command & Control.SchDoc
size B; CompanyName: Microchip Technology Inc.; Organization: Microchip Technology; Address1: 2355 West Chandler Blvd.; Address2: Chandler, AZ  85224; Address4: USA; DocumentNumber: 14; SheetNumber: 14; SheetTotal: 15; SheetTitle: User Command & Control
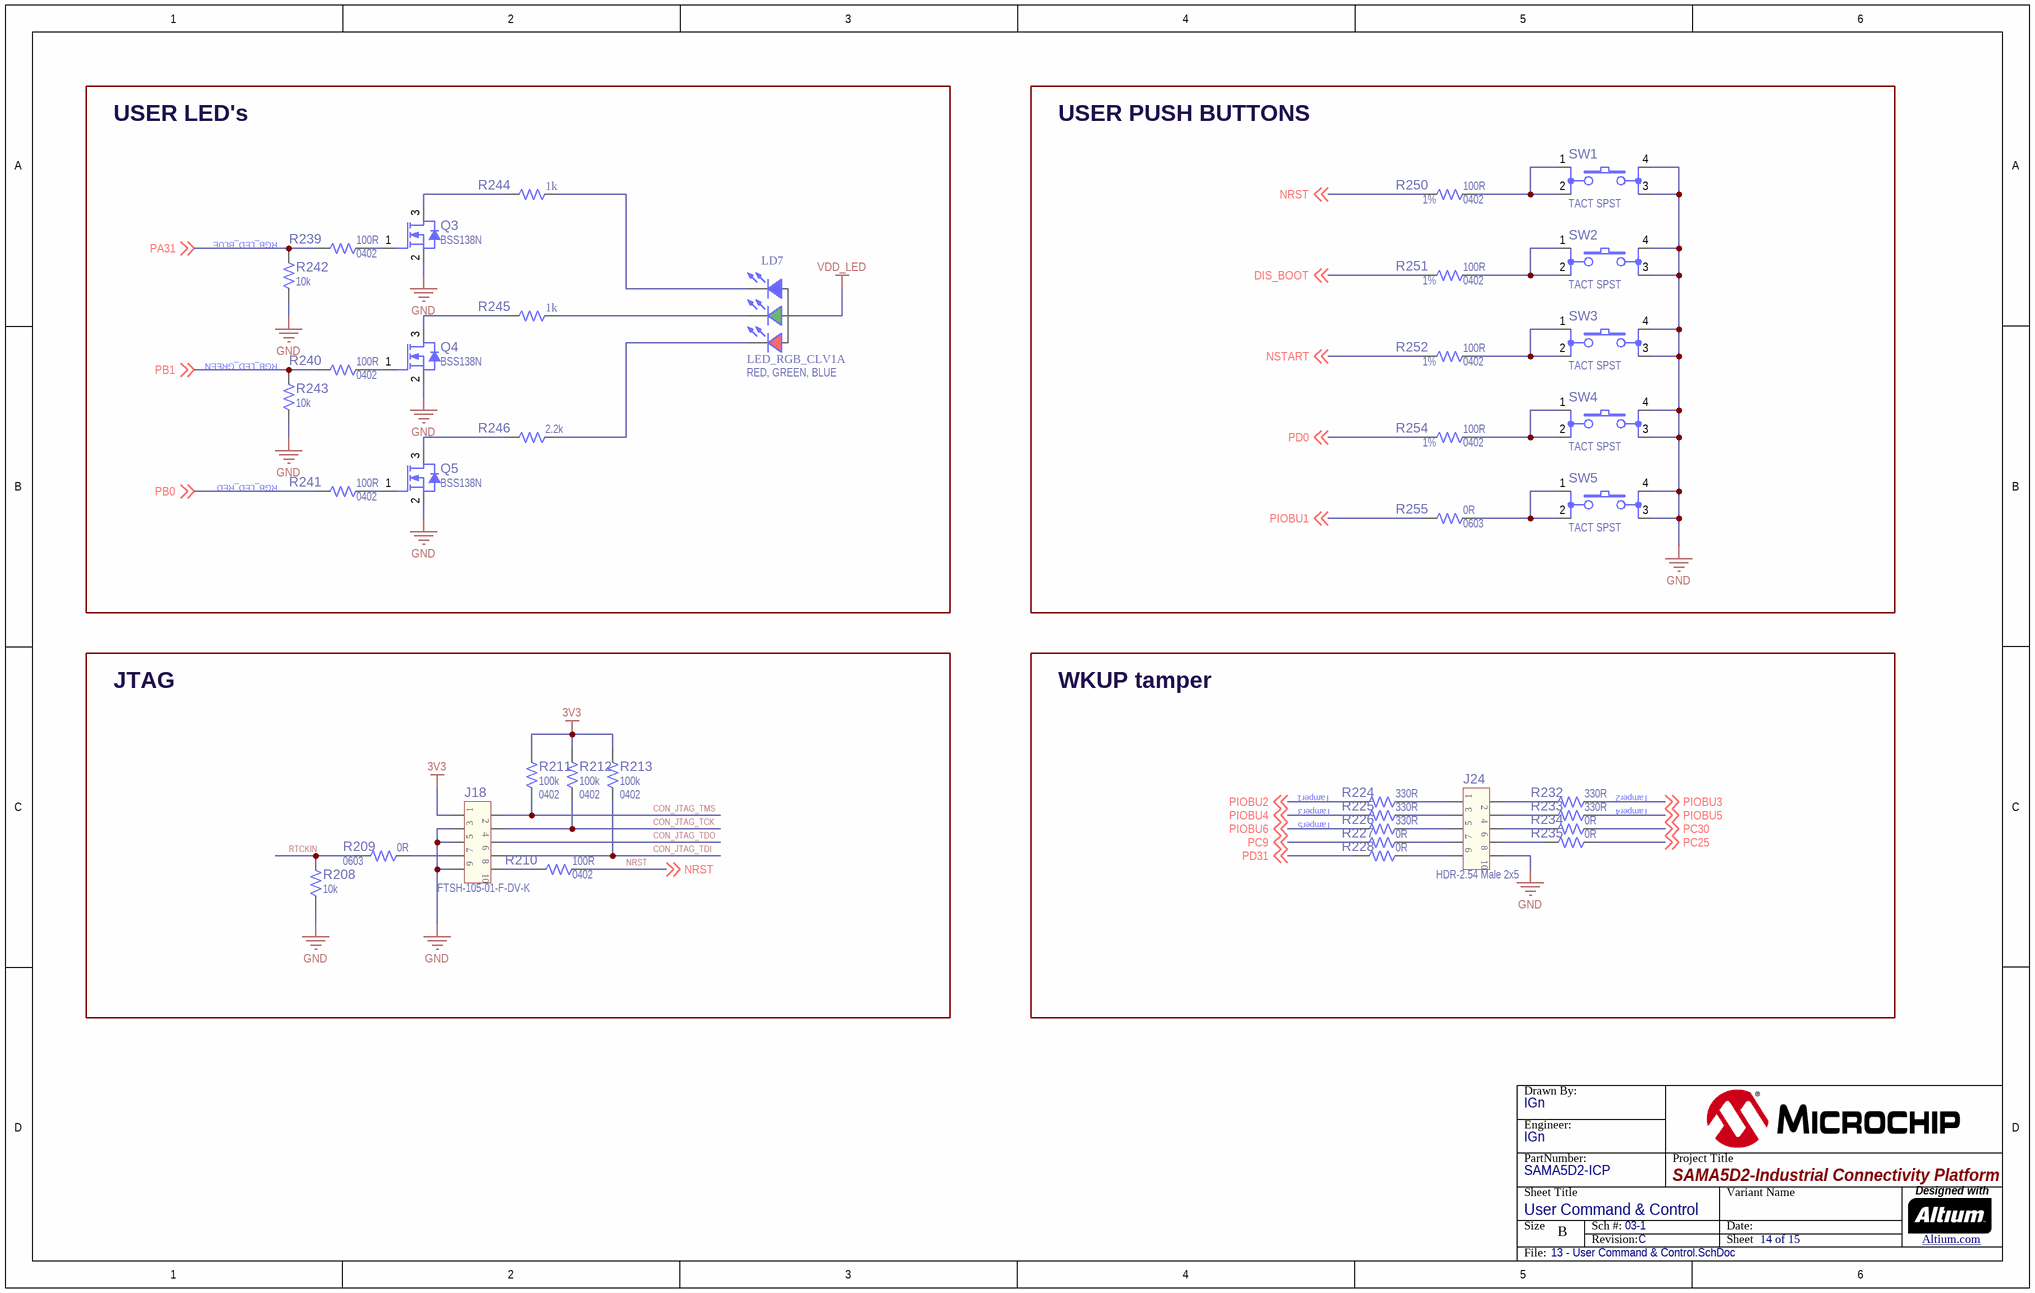
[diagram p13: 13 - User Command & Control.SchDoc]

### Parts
(Parts that share a designator on the sheet are numbered #1, #2 ... from top to bottom, then left to right.)
?#14  (no value)  (graphical)
J18  Manufacturer Part Number 1: FTSH-105-01-F-DV-K  [HDR_M_1.27_2x5_SMD_V_SAM_FTSH-105-01-F-DV-K]  (hidden comment: Header 2x5)
J24  value HDR-2.54 Male 2x5  [HDR_M_2.54_2x5_SMD_SAM_TSM-105-01-T-DV]  (hidden comment: Header 2x5)
LD7  LED_RGB_CLV1A  value RED, GREEN, BLUE  [PLCC-4_CLV1A-FKB]
Q3  value BSS138N  [SOT-23-3]  (hidden comment: Transistor MOS-N GSD)
Q4  value BSS138N  [SOT-23-3]  (hidden comment: Transistor MOS-N GSD)
Q5  value BSS138N  [SOT-23-3]  (hidden comment: Transistor MOS-N GSD)
R208  value 10k  [RES_C_0402]  (hidden comment: Resistor)
R209  value 0R  Package: 0603  [RES_C_0603]  (hidden comment: Resistor)
R210  value 100R  Package: 0402  [RES_C_0402]  (hidden comment: Resistor)
R211  value 100k  Package: 0402  [RES_C_0402]  (hidden comment: Resistor)
R212  value 100k  Package: 0402  [RES_C_0402]  (hidden comment: Resistor)
R213  value 100k  Package: 0402  [RES_C_0402]  (hidden comment: Resistor)
R224  value 330R  [RES_C_0603]  (hidden comment: Resistor)
R225  value 330R  [RES_C_0603]  (hidden comment: Resistor)
R226  value 330R  [RES_C_0603]  (hidden comment: Resistor)
R227  value 0R  [RES_C_0603]  (hidden comment: Resistor)
R228  value 0R  [RES_C_0603]  (hidden comment: Resistor)
R232  value 330R  [RES_C_0603]  (hidden comment: Resistor)
R233  value 330R  [RES_C_0603]  (hidden comment: Resistor)
R234  value 0R  [RES_C_0603]  (hidden comment: Resistor)
R235  value 0R  [RES_C_0603]  (hidden comment: Resistor)
R239  value 100R  Package: 0402  [RES_C_0402]  (hidden comment: Resistor)
R240  value 100R  Package: 0402  [RES_C_0402]  (hidden comment: Resistor)
R241  value 100R  Package: 0402  [RES_C_0402]  (hidden comment: Resistor)
R242  value 10k  [RES_C_0402]  (hidden comment: Resistor)
R243  value 10k  [RES_C_0402]  (hidden comment: Resistor)
R244  value 1k  [RES_C_0603]  (hidden comment: Resistor)
R245  value 1k  [RES_C_0603]  (hidden comment: Resistor)
R246  value 2.2k  [RES_C_0603]  (hidden comment: Resistor)
R250  value 100R  Package: 0402  Tolerance: 1%  [RES_C_0402]  (hidden comment: Resistor)
R251  value 100R  Package: 0402  Tolerance: 1%  [RES_C_0402]  (hidden comment: Resistor)
R252  value 100R  Package: 0402  Tolerance: 1%  [RES_C_0402]  (hidden comment: Resistor)
R254  value 100R  Package: 0402  Tolerance: 1%  [RES_C_0402]  (hidden comment: Resistor)
R255  value 0R  Package: 0603  [RES_C_0603]  (hidden comment: Resistor)
SW1  value TACT SPST  [SW_SMD_6mmX6mm_TL3301]  (hidden comment: Switch 4 Pin)
SW2  value TACT SPST  [SW_SMD_6mmX6mm_TL3301]  (hidden comment: Switch 4 Pin)
SW3  value TACT SPST  [SW_SMD_6mmX6mm_TL3301]  (hidden comment: Switch 4 Pin)
SW4  value TACT SPST  [SW_SMD_6mmX6mm_TL3301]  (hidden comment: Switch 4 Pin)
SW5  value TACT SPST  [SW_SMD_6mmX6mm_TL3301]  (hidden comment: Switch 4 Pin)

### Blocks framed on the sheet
USER LED's: LD7 Q3-Q5 R239-R246
USER PUSH BUTTONS: R250-R252 R254 R255 SW1-SW5
JTAG: J18 R208-R213
WKUP tamper: J24 R224-R228 R232-R235

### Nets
3V3: J18.1 R211.2 R212.2 R213.2
GND: J18.3 J18.5 J18.9 J24.10 Q3.2(S) Q4.2(S) Q5.2(S) R208.1 R242.1 R243.1 SW1.3 SW1.4 SW2.3 SW2.4 SW3.3 SW3.4 SW4.3 SW4.4 SW5.3 SW5.4
VDD_LED: LD7.2(A)
CON_JTAG_TCK: J18.4 R212.1
CON_JTAG_TDI: J18.8 R213.1
CON_JTAG_TDO: J18.6
CON_JTAG_TMS: J18.2 R211.1
DIS_BOOT: R251.1 ; off-sheet DIS_BOOT
NRST: R210.2 R250.1 ; off-sheet NRST
NSTART: R252.1 ; off-sheet NSTART
PA31: R239.1 R242.2 ; off-sheet PA31
PB0: R241.1 ; off-sheet PB0
PB1: R240.1 R243.2 ; off-sheet PB1
PC9: R227.2 ; off-sheet PC9
PC25: R235.1 ; off-sheet PC25
PC30: R234.2 ; off-sheet PC30
PD0: R254.1 ; off-sheet PD0
PD31: R228.2 ; off-sheet PD31
PIOBU1: R255.2 ; off-sheet PIOBU1
PIOBU2: R224.1 ; off-sheet PIOBU2
PIOBU3: R232.2 ; off-sheet PIOBU3
PIOBU4: R225.1 ; off-sheet PIOBU4
PIOBU5: R233.2 ; off-sheet PIOBU5
PIOBU6: R226.1 ; off-sheet PIOBU6
RTCKIN: R208.2 R209.2
NetJ18_7: J18.7 R209.1
NetJ18_10: J18.10 R210.1
NetJ24_1: J24.1 R224.2
NetJ24_2: J24.2 R232.1
NetJ24_3: J24.3 R225.2
NetJ24_4: J24.4 R233.1
NetJ24_5: J24.5 R226.2
NetJ24_6: J24.6 R234.1
NetJ24_7: J24.7 R227.1
NetJ24_8: J24.8 R235.2
NetJ24_9: J24.9 R228.1
NetLD7_1: LD7.1(Kr) R246.2
NetLD7_3: LD7.3(Kb) R244.2
NetLD7_4: LD7.4(Kg) R245.2
NetQ3_1: Q3.1(G) R239.2
NetQ3_3: Q3.3(D) R244.1
NetQ4_1: Q4.1(G) R240.2
NetQ4_3: Q4.3(D) R245.1
NetQ5_1: Q5.1(G) R241.2
NetQ5_3: Q5.3(D) R246.1
NetR250_2: R250.2 SW1.1 SW1.2
NetR251_2: R251.2 SW2.1 SW2.2
NetR252_2: R252.2 SW3.1 SW3.2
NetR254_2: R254.2 SW4.1 SW4.2
NetR255_1: R255.1 SW5.1 SW5.2

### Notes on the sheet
- (near R242) RGB_LED_BLUE
- (near R243) RGB_LED_GREEN
- RGB_LED_RED
- Tamper1
- Tamper3
- Tamper5
- Tamper2
- Tamper4

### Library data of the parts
?#14 = Title Block B
J18 = CON1047: CON HDR-1.27 Male 2x5 Gold 3.05MH SMD VERT; Manufacturer 1: Samtec; Dev Tools Status: Production; Owner: Tad Ahlvers; Populated: YES
J24 = CON1639: CON HDR-1.27 Male 2x5 Gold 3.05MH SMD VERT; Manufacturer 1: Samtec Inc.; Manufacturer Part Number 1: TSM-105-01-T-DV; Description_: CON HDR-2.54 Male 2x5 Tin 5.84MH SMD VERT; Dev Tools Status: Design; Owner: Gabor Bihari; Voltage: 475V; Current: 4.1A; Populated: DNP
LD7 = DIODE1214: Manufacturer 1: Cree Inc; Manufacturer Part Number 1: CLV1A-FKB-CK1N1G1BB7R4S3; Description_: DIO LED TRI RED, GREEN, BLUE 2V, 3.2V, 3.2V 20mA, 20mA, 20mA SMD 4-PLCC; Dev Tools Status: Production; Type: LED Tricolor; Forward Current: 20mA, 20mA, 20mA; Power: 130mW, 100mW, 100mW; Reverse Current: 10uA; Reverse Voltage: 5V; Owner: Randolph Sobrepena; Populated: YES
Q3-Q5 = TRA1223: Transistor MOS; Manufacturer 1: Infineon Technologies; Manufacturer Part Number 1: BSS138NH6327XTSA2; Description_: TRANS FET N-CH BSS138N 60V 230mA SOT23-3; Dev Tools Status: Production; Type: FET; Current: 230mA; Drain to Source Voltage: 60V; Gate to Source Voltage: 20V; Power: 0.36W; Owner: Dragos Danaila; Populated: YES
R208 R242 R243 = RSMT1019: as R107 on sheet 10 - CAN & WiFi BT
R209 = RSMT0001: Manufacturer 1: Panasonic; Manufacturer Part Number 1: ERJ-3GSY0R00V; Description_: RES TKF 0R 1/10W SMD 0603; Dev Tools Status: Production; Power: 1/10W; Populated: DNP
R210 R239-R241 = RES1436: as R257 on sheet 10 - CAN & WiFi BT
R211-R213 = RES1011: Manufacturer 1: Panasonic; Manufacturer Part Number 1: ERJ-2RKF1003X; Tolerance: 1%; Description_: RES TKF 100k 1% 1/10W SMD 0402; Dev Tools Status: Production; Voltage: 50V; Temperature Coeffcient: 100ppm/C; Power: 1/10W; Owner: Tad Ahlvers; Populated: YES
R224-R226 R232 R233 = RSMT0166: Manufacturer 1: Panasonic; Manufacturer Part Number 1: ERJ-3GEYJ331V; Tolerance: 5%; Description_: RES TKF 330R 5% 1/10W SMD 0603; Dev Tools Status: Production; Voltage: 75V; Temperature Coeffcient: 200ppm/C; Power: 1/10W; Populated: Yes
R227 R228 R234 R235 R255 = RSMT0001: as R109 on sheet 10 - CAN & WiFi BT
R244 R245 = RSMT0138: Manufacturer 1: Panasonic; Manufacturer Part Number 1: ERJ-3EKF1001V; Tolerance: 1%; Description_: RES TKF 1k 1% 1/10W SMD 0603; Dev Tools Status: Production; Voltage: 75V; Temperature Coeffcient: 100ppm/C; Power: 1/10W; Populated: Yes
R246 = RES1130: Manufacturer 1: Panasonic; Manufacturer Part Number 1: ERJ-3EKF2201V; Tolerance: 1%; Description_: RES TKF 2.2k 1% 1/10W SMD 0603; Dev Tools Status: Production; Voltage: 75V; Temperature Coeffcient: 100ppm/C; Power: 1/10W; Owner: Bogdan P (M91398); Populated: Yes
R250-R252 R254 = RES1436: Manufacturer 1: Panasonic Electronic Components; Manufacturer Part Number 1: ERJ-2RKF1000X; Description_: RES TKF 100R 1% 1/10W SMD 0402; Dev Tools Status: Production; Temperature Coeffcient: ±100ppm/°C; Power: 1/10W; Populated: YES
SW1-SW5 = SWITCH0077: Switch; Manufacturer 1: E-Switch; Manufacturer Part Number 1: TL3301AF260QG; Description_: SWITCH TACT SPST 12V 50mA TL3301AF260QG SMD; Dev Tools Status: Production; Voltage: 12V; Current: 50mA; Populated: Yes

## Sheet 14 - JLINK-OB Interface.SchDoc
size B; CompanyName: Microchip Technology Inc.; Organization: Microchip Technology; Address1: 2355 West Chandler Blvd.; Address2: Chandler, AZ  85224; Address4: USA; DocumentNumber: 15; SheetNumber: 15; SheetTotal: 15; SheetTitle: JLINK-OB Interface
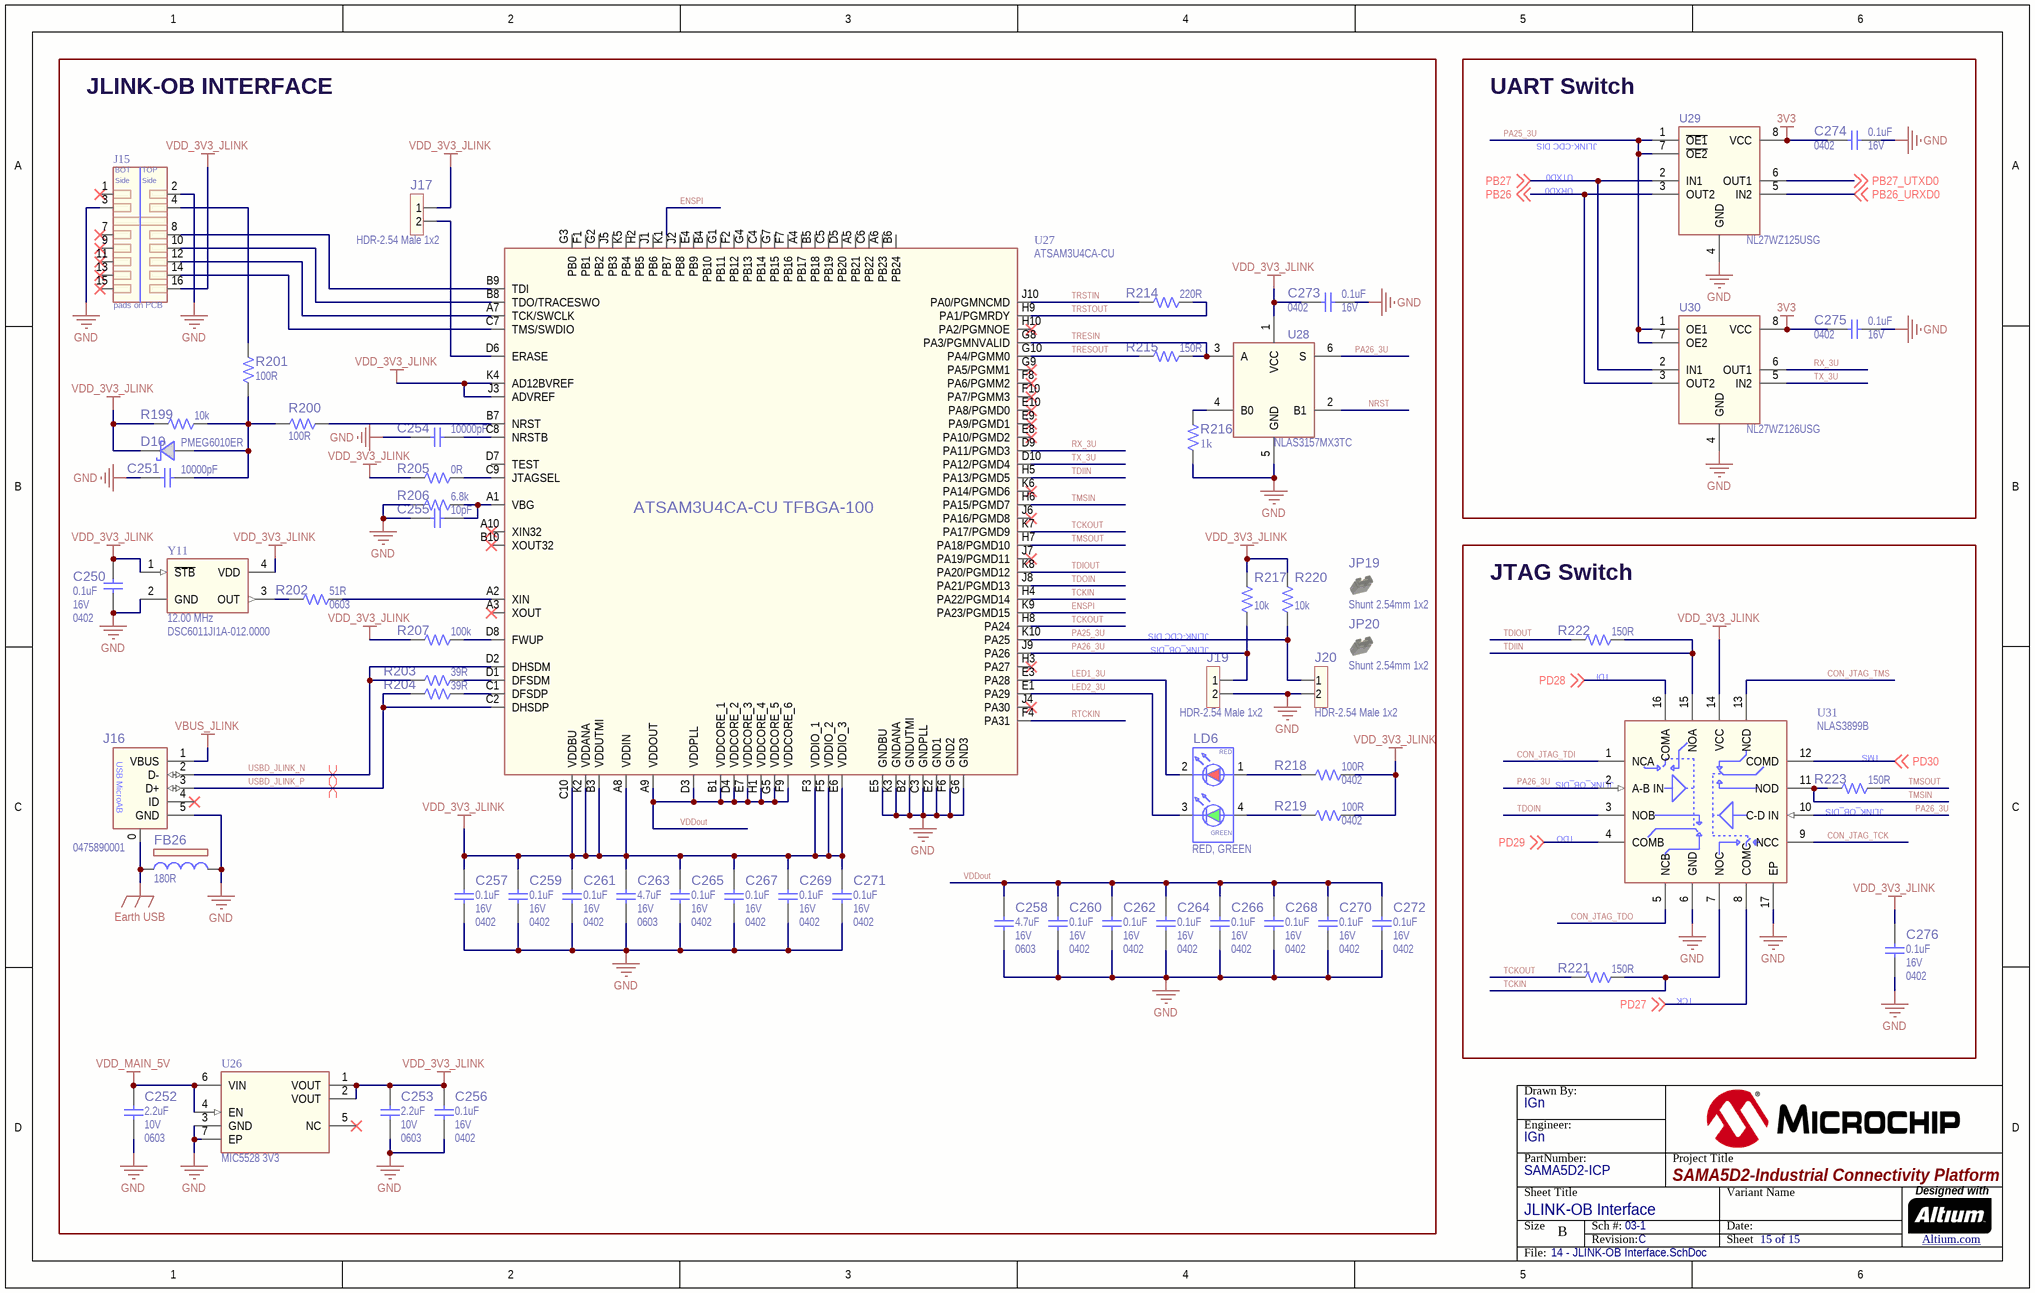
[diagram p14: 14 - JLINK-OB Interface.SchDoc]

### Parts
(Parts that share a designator on the sheet are numbered #1, #2 ... from top to bottom, then left to right.)
?#15  (no value)  (graphical)
C250  value 0.1uF  Voltage: 16V  Package: 0402  [CAP_C_0402]  (hidden comment: Capacitor NP)
C251  value 10000pF  [CAP_C_0402]  (hidden comment: Capacitor NP)
C252  value 2.2uF  Voltage: 10V  Package: 0603  [CAP_C_0603]  (hidden comment: Capacitor NP)
C253  value 2.2uF  Voltage: 10V  Package: 0603  [CAP_C_0603]  (hidden comment: Capacitor NP)
C254  value 10000pF  [CAP_C_0402]  (hidden comment: Capacitor NP)
C255  value 10pF  [CAP_C_0402]  (hidden comment: Capacitor NP)
C256  value 0.1uF  Voltage: 16V  Package: 0402  [CAP_C_0402]  (hidden comment: Capacitor NP)
C257  value 0.1uF  Voltage: 16V  Package: 0402  [CAP_C_0402]  (hidden comment: Capacitor NP)
C258  value 4.7uF  Voltage: 16V  Package: 0603  [CAP_C_0603]  (hidden comment: Capacitor NP)
C259  value 0.1uF  Voltage: 16V  Package: 0402  [CAP_C_0402]  (hidden comment: Capacitor NP)
C260  value 0.1uF  Voltage: 16V  Package: 0402  [CAP_C_0402]  (hidden comment: Capacitor NP)
C261  value 0.1uF  Voltage: 16V  Package: 0402  [CAP_C_0402]  (hidden comment: Capacitor NP)
C262  value 0.1uF  Voltage: 16V  Package: 0402  [CAP_C_0402]  (hidden comment: Capacitor NP)
C263  value 4.7uF  Voltage: 16V  Package: 0603  [CAP_C_0603]  (hidden comment: Capacitor NP)
C264  value 0.1uF  Voltage: 16V  Package: 0402  [CAP_C_0402]  (hidden comment: Capacitor NP)
C265  value 0.1uF  Voltage: 16V  Package: 0402  [CAP_C_0402]  (hidden comment: Capacitor NP)
C266  value 0.1uF  Voltage: 16V  Package: 0402  [CAP_C_0402]  (hidden comment: Capacitor NP)
C267  value 0.1uF  Voltage: 16V  Package: 0402  [CAP_C_0402]  (hidden comment: Capacitor NP)
C268  value 0.1uF  Voltage: 16V  Package: 0402  [CAP_C_0402]  (hidden comment: Capacitor NP)
C269  value 0.1uF  Voltage: 16V  Package: 0402  [CAP_C_0402]  (hidden comment: Capacitor NP)
C270  value 0.1uF  Voltage: 16V  Package: 0402  [CAP_C_0402]  (hidden comment: Capacitor NP)
C271  value 0.1uF  Voltage: 16V  Package: 0402  [CAP_C_0402]  (hidden comment: Capacitor NP)
C272  value 0.1uF  Voltage: 16V  Package: 0402  [CAP_C_0402]  (hidden comment: Capacitor NP)
C273  value 0.1uF  Voltage: 16V  Package: 0402  [CAP_C_0402]  (hidden comment: Capacitor NP)
C274  value 0.1uF  Voltage: 16V  Package: 0402  [CAP_C_0402]  (hidden comment: Capacitor NP)
C275  value 0.1uF  Voltage: 16V  Package: 0402  [CAP_C_0402]  (hidden comment: Capacitor NP)
C276  value 0.1uF  Voltage: 16V  Package: 0402  [CAP_C_0402]  (hidden comment: Capacitor NP)
D10  value PMEG6010ER  [SOD-123]  (hidden comment: Diode Schottky)
FB26  value 180R  [IND_C_0603]  (hidden comment: Ferrite Bead)
J15  pads on PCB  [CON_EDGE-CARD_PCB_RA_MEC1-108-02-F-D-RA1-SL]
J16  value 0475890001  [CON_USB_Micro-AB_SMD_RA_MOLEX_0475890001]  (hidden comment: CON USB2.0 Mini_Micro)
J17  value HDR-2.54 Male 1x2  [HDR_M_2.54_1x2]  (hidden comment: Header 1x2)
J19  value HDR-2.54 Male 1x2  [HDR_M_2.54_1x2]  (hidden comment: Header 1x2)
J20  value HDR-2.54 Male 1x2  [HDR_M_2.54_1x2]  (hidden comment: Header 1x2)
JP19  value Shunt 2.54mm 1x2  [Jumper_Mechanical]  (hidden comment: Jumper Mechanical)  (mechanical)
JP20  value Shunt 2.54mm 1x2  [Jumper_Mechanical]  (hidden comment: Jumper Mechanical)  (mechanical)
LD6  value RED, GREEN  [LED_DUAL_SMD_2x1.25mm]  (hidden comment: LED DUAL 4 pin)
R199  value 10k  [RES_C_0402]  (hidden comment: Resistor)
R200  value 100R  [RES_C_0402]  (hidden comment: Resistor)
R201  value 100R  [RES_C_0402]  (hidden comment: Resistor)
R202  value 51R  Package: 0603  [RES_C_0603]  (hidden comment: Resistor)
R203  value 39R  [RES_C_0402]  (hidden comment: Resistor)
R204  value 39R  [RES_C_0402]  (hidden comment: Resistor)
R205  value 0R  [RES_C_0402]  (hidden comment: Resistor)
R206  value 6.8k  [RES_C_0402]  (hidden comment: Resistor)
R207  value 100k  [RES_C_0402]  (hidden comment: Resistor)
R214  value 220R  [RES_C_0402]  (hidden comment: Resistor)
R215  value 150R  [RES_C_0402]  (hidden comment: Resistor)
R216  value 1k  [RES_C_0603]  (hidden comment: Resistor)
R217  value 10k  [RES_C_0402]  (hidden comment: Resistor)
R218  value 100R  Package: 0402  [RES_C_0402]  (hidden comment: Resistor)
R219  value 100R  Package: 0402  [RES_C_0402]  (hidden comment: Resistor)
R220  value 10k  [RES_C_0402]  (hidden comment: Resistor)
R221  value 150R  [RES_C_0402]  (hidden comment: Resistor)
R222  value 150R  [RES_C_0402]  (hidden comment: Resistor)
R223  value 150R  [RES_C_0402]  (hidden comment: Resistor)
U26  value MIC5528 3V3  [DFN-6_1.2x1.2]  (hidden comment: MIC5528MT DFN-6)
U27  ATSAM3U4CA-CU TFBGA-100  value ATSAM3U4CA-CU  [TFBGA-100_P0.8_9x9x1.1]
U28  value NLAS3157MX3TC  [ULLGA-6_1X1]  (hidden comment: NLAS3157 ULLGA-6)
U29  value NL27WZ125USG  [US-8]  (hidden comment: NL27WZ125 US-8)
U30  value NL27WZ126USG  [US-8]  (hidden comment: NL27WZ126 US-8)
U31  value NLAS3899B  [QFN-16_3X3_EP1.4X1.4]  (hidden comment: NLAS3899B QFN16)
Y11  value 12.00 MHz  Manufacturer Part Number 1: DSC6011JI1A-012.0000  [OSCILLATOR_DSC60000L2.5W2.0H0.89]  (hidden comment: OSCILLATOR DSC60XX)

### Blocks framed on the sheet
JLINK-OB INTERFACE: C250-C273 D10 FB26 J15-J17 J19 J20 JP19 JP20 LD6 R199-R207 R214-R220 U26-U28 Y11
UART Switch: C274 C275 U29 U30
JTAG Switch: C276 R221-R223 U31

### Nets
3V3: C274.2 C275.2 U29.8(VCC) U30.8(VCC)
Earth USB: FB26.1 J16.0(SHLD)
GND: C250.1 C251.1 C252.1 C253.1 C254.1 C255.1 C256.1 C257.1 C258.1 C259.1 C260.1 C261.1 C262.1 C263.1 C264.1 C265.1 C266.1 C267.1 C268.1 C269.1 C270.1 C271.1 C272.1 C273.1 C274.1 C275.1 C276.1 FB26.2 J15.2 J15.3 J16.5(GND) J19.2 J20.2 R206.1 R216.1 U26.3(GND) U26.7(EP) U27.B2(GNDUTMI) U27.C3(GNDPLL) U27.E2(GND1) U27.E5(GNDBU) U27.F6(GND2) U27.G6(GND3) U27.K3(GNDANA) U28.5(GND) U29.4(GND) U30.4(GND) U31.6(GND) U31.17(EP) Y11.2(GND)
VBUS_JLINK: J16.1(VBUS)
VDD_3V3_JLINK: C250.2 C253.2 C256.2 C257.2 C259.2 C261.2 C263.2 C265.2 C267.2 C269.2 C271.2 C273.2 C276.2 D10.2(K) J15.16 J17.1 R199.2 R205.1 R207.1 R217.2 R218.2 R219.2 R220.2 U26.1(VOUT) U26.2(VOUT) U27.A8(VDDIN) U27.B3(VDDUTMI) U27.C10(VDDBU) U27.E6(VDDIO_3) U27.F3(VDDIO_1) U27.F5(VDDIO_2) U27.J3(ADVREF) U27.K2(VDDANA) U27.K4(AD12BVREF) U28.1(VCC) U31.14(VCC) Y11.1(~{STB}) Y11.4(VDD)
VDD_MAIN_5V: C252.2 U26.4(EN) U26.6(VIN)
CON_JTAG_TCK: U31.9(NCC)
CON_JTAG_TDI: U31.1(NCA)
CON_JTAG_TDO: U31.5(NCB)
CON_JTAG_TMS: U31.13(NCD)
ENSPI: U27.K1(PB7) U27.K9(PA23/PGMD15)
LED1_3U: LD6.2(K1) U27.E3(PA28)
LED2_3U: LD6.3(K2) U27.E1(PA29)
NRST: U28.2(B1)
PA25_3U: J20.1 R220.1 U27.K10(PA25) U29.1(~{OE1}) U29.7(~{OE2}) U30.1(OE1) U30.7(OE2)
PA26_3U: J19.1 R217.1 U27.J9(PA26) U28.6(S) U31.2(A-B_IN) U31.10(C-D_IN)
PB26: U29.3(OUT2) U30.3(OUT2) ; off-sheet PB26
PB26_URXD0: U29.5(IN2) ; off-sheet PB26_URXD0
PB27: U29.2(IN1) U30.2(IN1) ; off-sheet PB27
PB27_UTXD0: U29.6(OUT1) ; off-sheet PB27_UTXD0
PD27: U31.8(COMC) ; off-sheet PD27
PD28: U31.16(COMA) ; off-sheet PD28
PD29: U31.4(COMB) ; off-sheet PD29
PD30: U31.12(COMD) ; off-sheet PD30
RTCKIN: U27.F4(PA31)
RX_3U: U27.D9(PA11/PGMD3) U30.6(OUT1)
TCKIN: R221.2 U27.H4(PA22/PGMD14) U31.7(NOC)
TCKOUT: R221.1 U27.H8(PA24) U27.K7(PA17/PGMD9)
TDIIN: R222.2 U27.H5(PA13/PGMD5) U31.15(NOA)
TDIOUT: R222.1 U27.K8(PA20/PGMD12)
TDOIN: U27.J8(PA21/PGMD13) U31.3(NOB)
TMSIN: R223.1 U27.H6(PA15/PGMD7) U31.11(NOD)
TMSOUT: R223.2 U27.H7(PA18/PGMD10)
TRESIN: R215.2 U27.G8(PA3/PGMNVALID) U28.3(A)
TRESOUT: R215.1 U27.G10(PA4/PGMM0)
TRSTIN: R214.1 U27.J10(PA0/PGMNCMD)
TRSTOUT: R214.2 U27.H9(PA1/PGMRDY)
TX_3U: U27.D10(PA12/PGMD4) U30.5(IN2)
USBD_JLINK_N: J16.2(D-) R203.1 U27.D2(DHSDM)
USBD_JLINK_P: J16.3(D+) R204.1 U27.C2(DHSDP)
VDDout: C258.2 C260.2 C262.2 C264.2 C266.2 C268.2 C270.2 C272.2 U27.A9(VDDOUT) U27.B1(VDDCORE_1) U27.D3(VDDPLL) U27.D4(VDDCORE_2) U27.E7(VDDCORE_3) U27.F9(VDDCORE_6) U27.G5(VDDCORE_5) U27.H1(VDDCORE_4)
NetC251_2: C251.2 D10.1(A) R199.1 R200.1 R201.2
NetC254_2: C254.2 U27.C8(NRSTB)
NetC255_2: C255.2 R206.2 U27.A1(VBG)
NetJ15_4: J15.4 R201.1
NetJ15_8: J15.8 U27.B9(TDI)
NetJ15_10: J15.10 U27.B8(TDO/TRACESWO)
NetJ15_12: J15.12 U27.A7(TCK/SWCLK)
NetJ15_14: J15.14 U27.C7(TMS/SWDIO)
NetJ17_2: J17.2 U27.D6(ERASE)
NetLD6_1: LD6.1(A1) R218.1
NetLD6_4: LD6.4(A2) R219.1
NetR200_2: R200.2 U27.B7(NRST)
NetR202_1: R202.1 Y11.3(OUT)
NetR202_2: R202.2 U27.A2(XIN)
NetR203_2: R203.2 U27.D1(DFSDM)
NetR204_2: R204.2 U27.C1(DFSDP)
NetR205_2: R205.2 U27.C9(JTAGSEL)
NetR207_2: R207.2 U27.D8(FWUP)
NetR216_2: R216.2 U28.4(B0)

Not connected (* = marked no-connect by the designer): J15 1* 7* 9* 11* 13* 15*; J16 4(ID)*; U26 5(NC)*; U27 A3(XOUT)* A4(PB17) A5(PB21) A6(PB23) A10(XIN32)* B4(PB10) B5(PB18) B6(PB24) B10(XOUT32)* C4(PB14) C5(PB19) C6(PB22) D5(PB20) D7(TEST) E4(PB9) E8(PA10/PGMD2)* E9(PA9/PGMD1)* E10(PA8/PGMD0)* F1(PB1) F2(PB12) F7(PB16) F8(PA6/PGMM2)* F10(PA7/PGMM3)* G1(PB11) G2(PB2) G3(PB0) G4(PB13) G7(PB15) G9(PA5/PGMM1)* H2(PB5) H3(PA27)* H10(PA2/PGMNOE)* J1(PB6) J2(PB8) J4(PA30)* J5(PB3) J6(PA16/PGMD8)* J7(PA19/PGMD11)* K5(PB4) K6(PA14/PGMD6)*

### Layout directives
differential pair: USBD_JLINK_N, USBD_JLINK_P

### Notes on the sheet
- UTXD0
- JLINK-CDC DIS
- URXD0
- (near J19) JLINK_OB_DIS
- TDI
- (near J16) USB MicroAB
- (near U31) JLINK_OB_DIS
- (near R223) TMS
- (near U31) TDO
- (near R223) JLINK_OB_DIS
- TCK

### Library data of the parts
?#15 = Title Block B
C250 C256 C257 C259-C262 C264-C276 = CAP1033: as C129-C132 on sheet 10 - CAN & WiFi BT
C251 C254 = CAP1071: Capacitor; Manufacturer 1: Yageo; Manufacturer Part Number 1: CC0402KRX7R9BB103; Voltage: 50V; Description_: CAP CER 10000pF 50V 10% X7R SMD 0402; Dev Tools Status: Production; Tolerance: 10%; Temperature Coeffcient: X7R; Type: Ceramic; Owner: Tad Ahlvers; Populated: YES
C252 C253 = CAP0559: Capacitor; Manufacturer 1: Murata; Manufacturer Part Number 1: GRM188R71A225KE15D; Description_: CAP CER 2.2uF 10V 10% X7R SMD 0603; Dev Tools Status: Production; Tolerance: 10%; Temperature Coeffcient: X7R; Type: Ceramic; Populated: Yes
C255 = CAP0613: Capacitor; Manufacturer 1: Murata; Manufacturer Part Number 1: GRM1555C1H100JZ01D; Voltage: 50V; Description_: CAP CER 10pF 50V 5% NP0 SMD 0402; Dev Tools Status: Production; Tolerance: 5%; Temperature Coeffcient: NP0; Type: Ceramic; Populated: Yes
C258 C263 = CAP1288: Capacitor; Manufacturer 1: TDK Corporation; Manufacturer Part Number 1: C1608X5R1C475K080AC; Description_: CAP CER 4.7uF 16V 10% X5R SMD 0603; Dev Tools Status: Production; Tolerance: 10%; Temperature Coeffcient: X5R; Type: Ceramic; Owner: Jairuz Agang-ang; Populated: YES
D10 = DIODE1254: DIO SCTKY RB160M-60TR 550mV 1A 60V SMD SOD-123F; Manufacturer 1: NXP Semiconductors                                                                               NXP Semiconductors; Manufacturer Part Number 1: PMEG6010ER,115; Description_: DIODE SCTKY PMEG6010ER 530mV 1A 60V SMD SOD-123; Dev Tools Status: Design; Type: Schottky Single; Power: 0.95W; Reverse Current: 60uA; Reverse Recovery Time: 500ns; Owner: Sorin Stanoaia; Populated: YES
FB26 = IND1453: as FB27 on sheet 10 - CAN & WiFi BT
J15 = CON1674: CON_PCB_MEC1-108-02-F-D-RA1-SL; Manufacturer 1: Samtec Inc.; Description_: CON EDGE MEC1 1mm 14P Male PCB VERT; Dev Tools Status: Design; Owner: Dragos Danaila; Current: 1.6A; Populated: YES
J16 = CON1753: Connector USB Mini; Manufacturer 1: Molex, LLC; Description_: CON USB2.0 MICRO-AB FEMALE SMD R/A; Dev Tools Status: Design; Owner: Dragos Danaila; Voltage: 30VAC; Current: 1A, 1.8A; Populated: YES
J17 = CON1108: Manufacturer 1: FCI; Manufacturer Part Number 1: 77311-118-02LF; Description_: CON HDR-2.54 Male 1x2 Gold 5.84MH TH VERT; Dev Tools Status: Production; Owner: Bogdan P (M91398); Populated: DNP
J19 J20 = CON1108: Manufacturer 1: FCI; Manufacturer Part Number 1: 77311-118-02LF; Description_: CON HDR-2.54 Male 1x2 Gold 5.84MH TH VERT; Dev Tools Status: Production; Owner: Bogdan P (M91398); Populated: Yes
JP19 JP20 = HW1006: Manufacturer 1: 3M; Manufacturer Part Number 1: 969102-0000-DA; MCHP-ID: HW1006; Description_: MECH HW JUMPER 2.54mm 1x2; Dev Tools Status: Production; Owner: Mike Ragsdale; Populated: MECH
LD6 = DIODE1110: as LD8 on sheet 10 - CAN & WiFi BT
R199 R217 R220 = RSMT1019: as R107 on sheet 10 - CAN & WiFi BT
R200 R201 R218 R219 = RES1436: as R257 on sheet 10 - CAN & WiFi BT
R202 = RES1384: Manufacturer 1: Yageo; Manufacturer Part Number 1: RC0603FR-0751RL; Tolerance: 1%; Description_: RES TKF 51R 1% 1/10W SMD 0603; Dev Tools Status: Production; Voltage: 50V; Temperature Coeffcient: 100ppm/C; Circuit Type: Isolated; Power: 1/10W; Owner: Jairuz Agang-ang; Populated: YES
R203 R204 = RES1800: Manufacturer 1: Yageo; Manufacturer Part Number 1: RC0402FR-0739RL; Tolerance: 1%; Description_: RES TKF 39R 1% 1/16W SMD 0402; Dev Tools Status: Production; Circuit Type: Single; Power: 1/16W; Owner: Sompoch Loboonlert; Populated: YES
R205 = RSMT0730: Manufacturer 1: Panasonic; Manufacturer Part Number 1: ERJ-2GE0R00X; Description_: RES TKF 0R SMD 0402; Dev Tools Status: Production; Power: 1/10W; Populated: DNP
R206 = RSMT1211: Manufacturer 1: Vishay Dale; Manufacturer Part Number 1: CRCW04026K80FKED; Tolerance: 1%; Description_: RES TKF 6.8k 1% 1/16W SMD 0402; Dev Tools Status: Production; Voltage: 50V; Temperature Coeffcient: 100ppm/C; Power: 1/16W; Owner: Dragos Danaila; Populated: YES
R207 = RES1011: as R211-R213 on sheet 13 - User Command & Control
R214 = RES1008: Manufacturer 1: Panasonic - ECG; Manufacturer Part Number 1: ERJ-2GEJ221X; Tolerance: 5%; Description_: RES TKF 220R 5% 1/10W SMD 0402; Dev Tools Status: Production; Voltage: 50V; Temperature Coeffcient: 200ppm/C; Power: 1/10W; Owner: Tad Ahlvers; Populated: YES
R215 R221-R223 = RSMT1167: Manufacturer 1: Vishay Dale; Manufacturer Part Number 1: CRCW0402150RFKED; Description_: RES TKF 150R 1% 1/16W MF 0402; Dev Tools Status: Production; Owner: Jamus Griego; Populated: YES
R216 = RSMT0138: as R244 on sheet 13 - User Command & Control
U26 = MIC6905: Manufacturer 1: Microchip Technology; Manufacturer Part Number 1: MIC5528-3.3YMT-TR; Description_: MCHP ANALOG LDO 3.3V MIC5528-3.3YMT-TR 6-TDFN; MAPS Description: Single, 500mA LDO w/ Auto Discharge & Internal Enable Pulldown; Dev Tools Status: Production; Owner: Tim Moffat; MPC: TKFC1YHHAA02; LeadContent: Pb-FREE; PackingMedia: T/R; Stage: REL; LeadCount: 6; PackageWidth: 1.2x1.2x0.6mm; ForceMinOrderQtyMult: True; MinOrderQty: 1; TempRange: -40C to +125C; tblDeviceFamilyID: 7519; Populated: YES
U27 = MIC7470: Manufacturer 1: Microchip Technology; Description_: MCHP MCU 32-BIT 96MHz 256kB 56kB ATSAM3U4CA-CU 100BGA; MAPS Description: TFBGA,GREEN,IND TEMP,MRL A; Dev Tools Status: Design; Owner: Dragos Danaila; MPC: 58Z247A2BC02; LeadContent: Pb-FREE; TempRange: -40C to +85C; Stage: REL; PackageWidth: 9x9x1.2mm; PackingMedia: TRAY; ForceMinOrderQtyMult: True; MinOrderQty: 260; LeadCount: 100; Program Memory KBytes: 256; Program Memory KWords: 64; Ram: 51200; EEPROM: 0; IOPins: 57; MaxSpeed: 96; OscillatorMHz: 4,8,12Mhz,32Khz; ADC Channels: 8; ADCBit: 12; USART: 4; I2C: 1; Input Capture: 6; CapTouchCH: 28; DigitalTimerQty_16bit: 3; Populated: YES
U28 = IC1519: SWITCH SPDT; Manufacturer 1: ON Semiconductor; Manufacturer Part Number 1: NLAS3157MX3TCG; MCHP-ID: IC1519; Description_: IC SWITCHER NLAS3157MX3TCG SPDT 9.9 OHM ULLGA-6; Dev Tools Status: Design; Vin: 3.3V; Owner: Ciprian Abramov; Populated: YES
U29 = IC1512: BUFFER DL TRI-ST NON-INV; Manufacturer 1: ON Semiconductor; MCHP-ID: IC1512; Description_: IC BUFFER NL27WZ125USG DUAL TRI-ST NON-INV US-8; Dev Tools Status: Design; Vin: 5V; Owner: Ciprian Abramov; Populated: YES
U30 = IC1514: BUFFER DL TRI-ST NON-INV; Manufacturer 1: ON Semiconductor; MCHP-ID: IC1514; Description_: IC BUFFER NL27WZ126USG DUAL TRI-ST NON-INV US-8; Dev Tools Status: Design; Vin: 5V; Owner: Ciprian Abramov; Populated: YES
U31 = IC1436: IC SWITCHER NLAS3899B Analog Switch QFN16; Manufacturer 1: ON Semiconductor; Manufacturer Part Number 1: NLAS3899BMNTWG; MCHP-ID: IC1436; Dev Tools Status: Production; Vin: 4.3V; Owner: Dragos Danaila; Populated: YES
Y11 = MIC7210: Manufacturer 1: Microchip Technology Inc; Description_: MCHP CLOCK OSCILLATOR SINGLE 12.000MHZ DSC6011JI1A-012.0000 VLGA; Dev Tools Status: Production; Owner: Tim Moffat; Populated: YES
